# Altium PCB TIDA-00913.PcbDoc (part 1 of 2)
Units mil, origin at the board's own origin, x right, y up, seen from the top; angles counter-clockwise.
Board outline 3117.8 x 2115.91 mil, 4 copper layers (Top Layer, Internal Layer 1, Internal Layer 2, Bottom Layer), stack 61.6 mil thick; 181 components, 89 nets, 500 pads, 191 vias.
Unrouted connection lines stored in the file: 2.
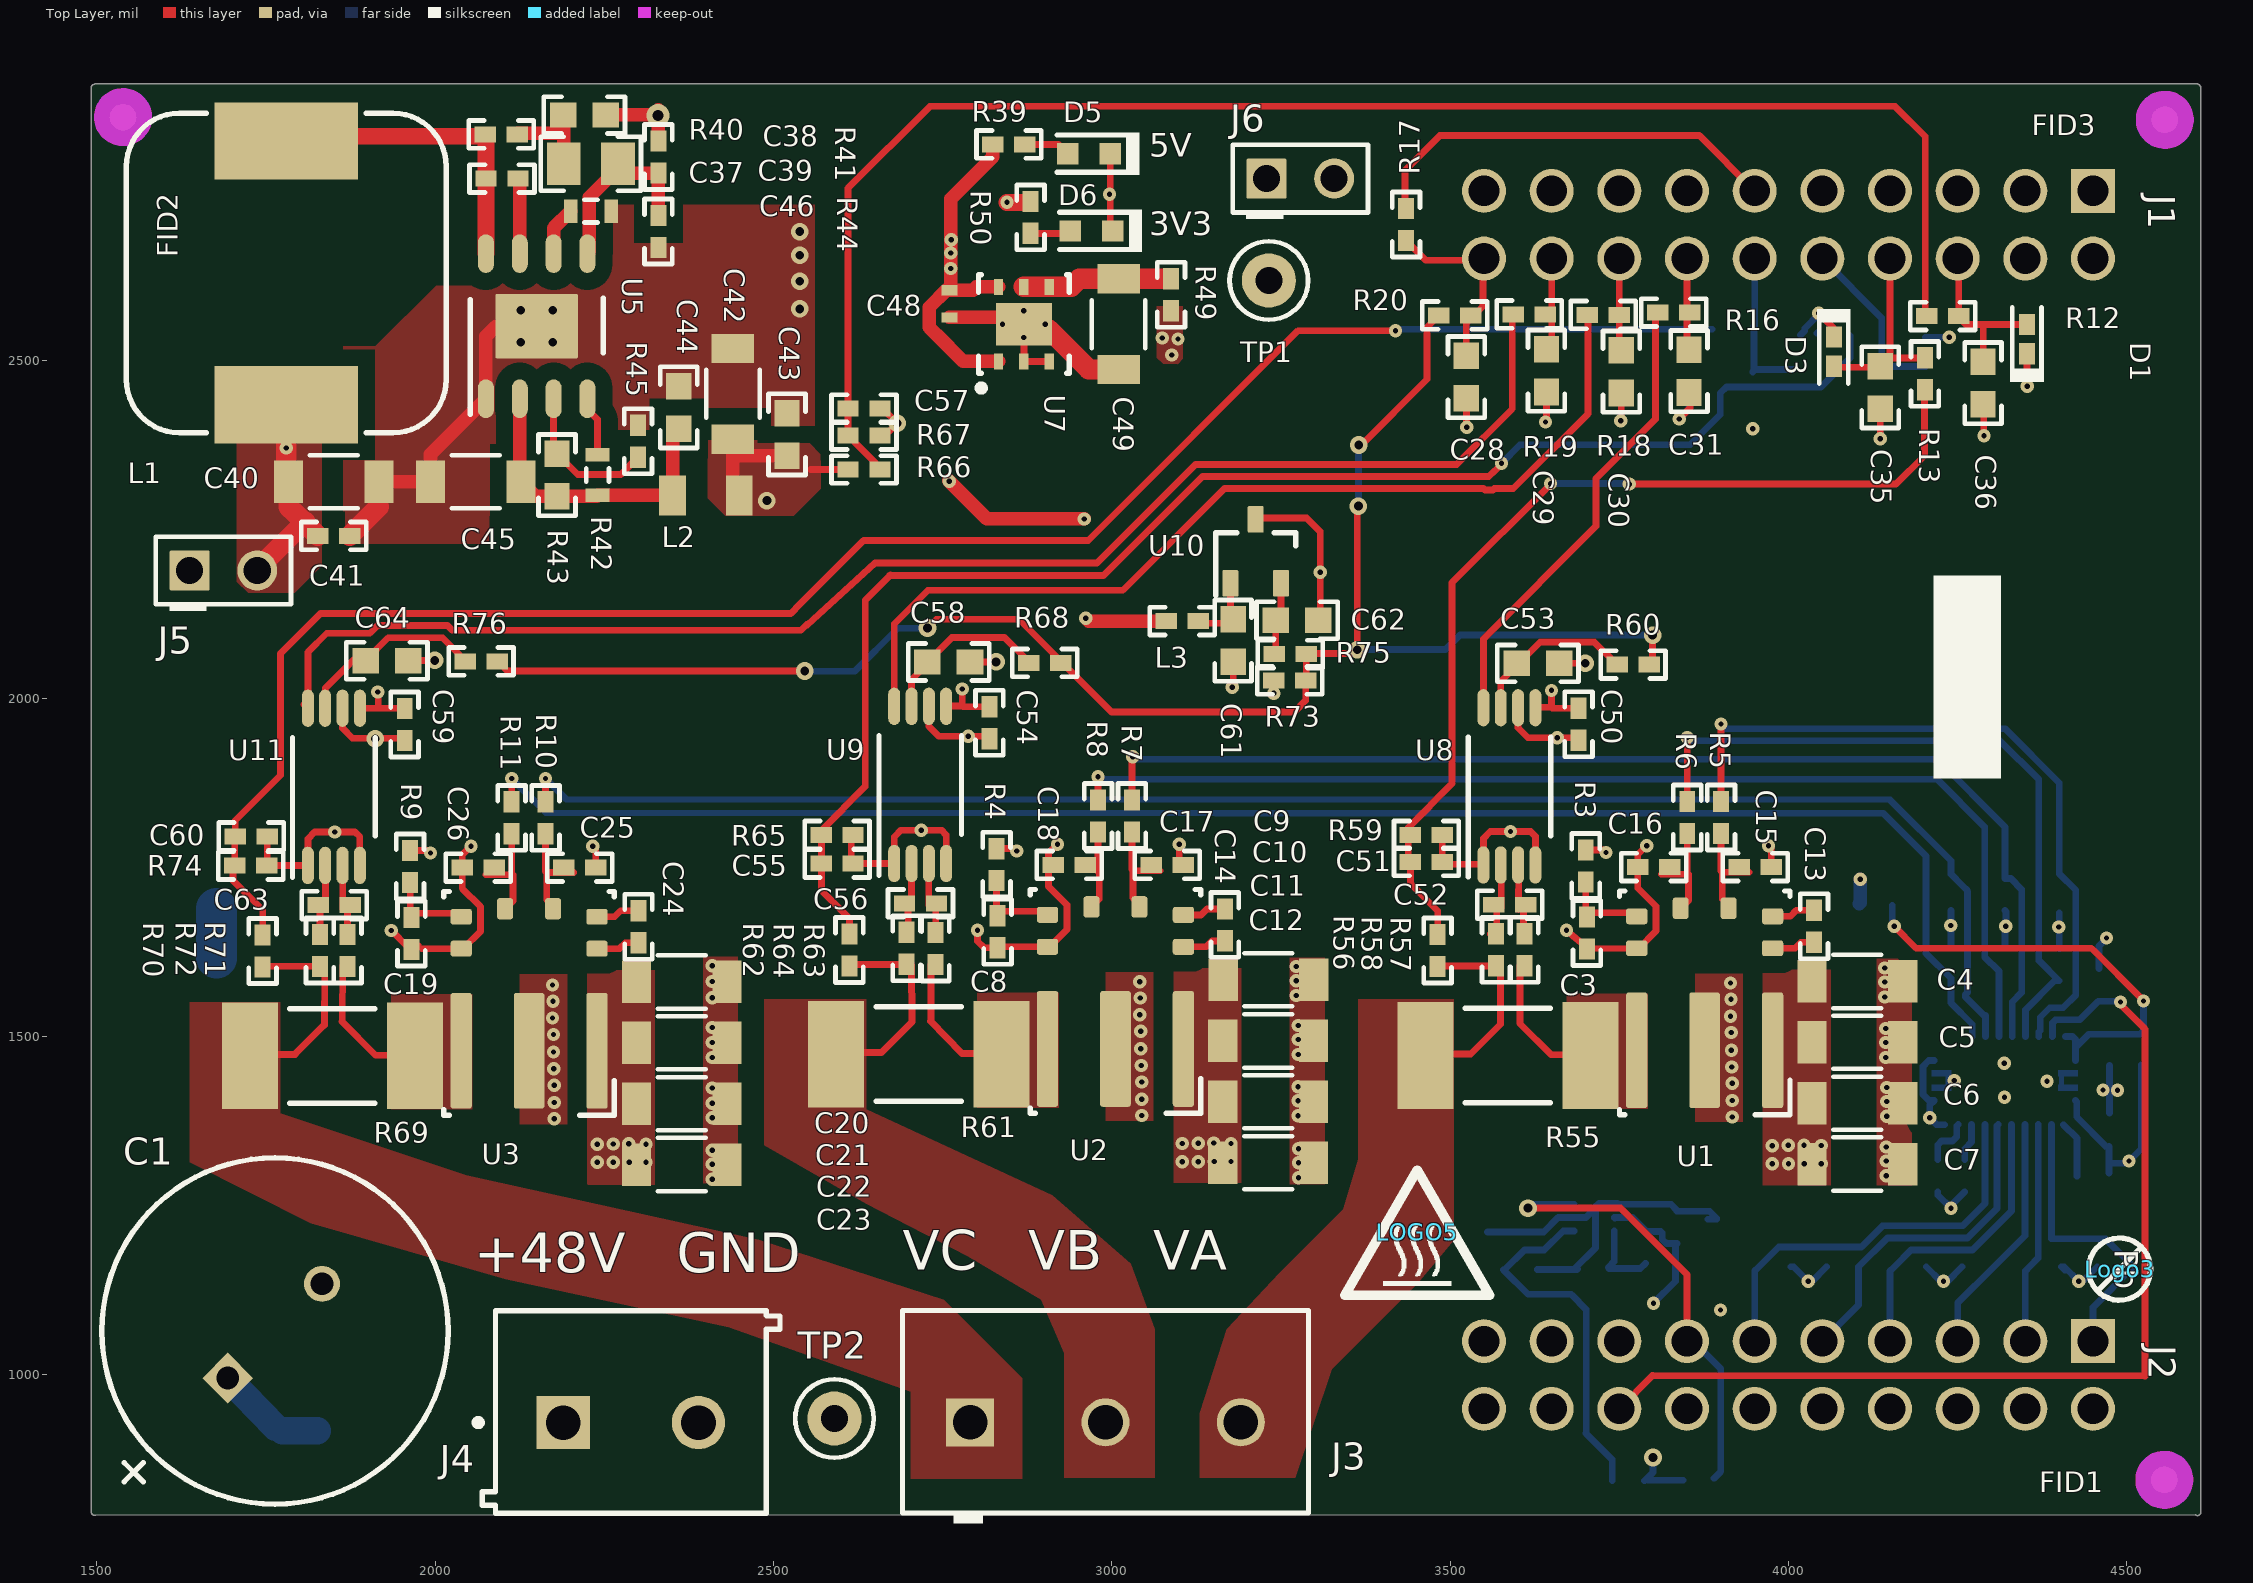
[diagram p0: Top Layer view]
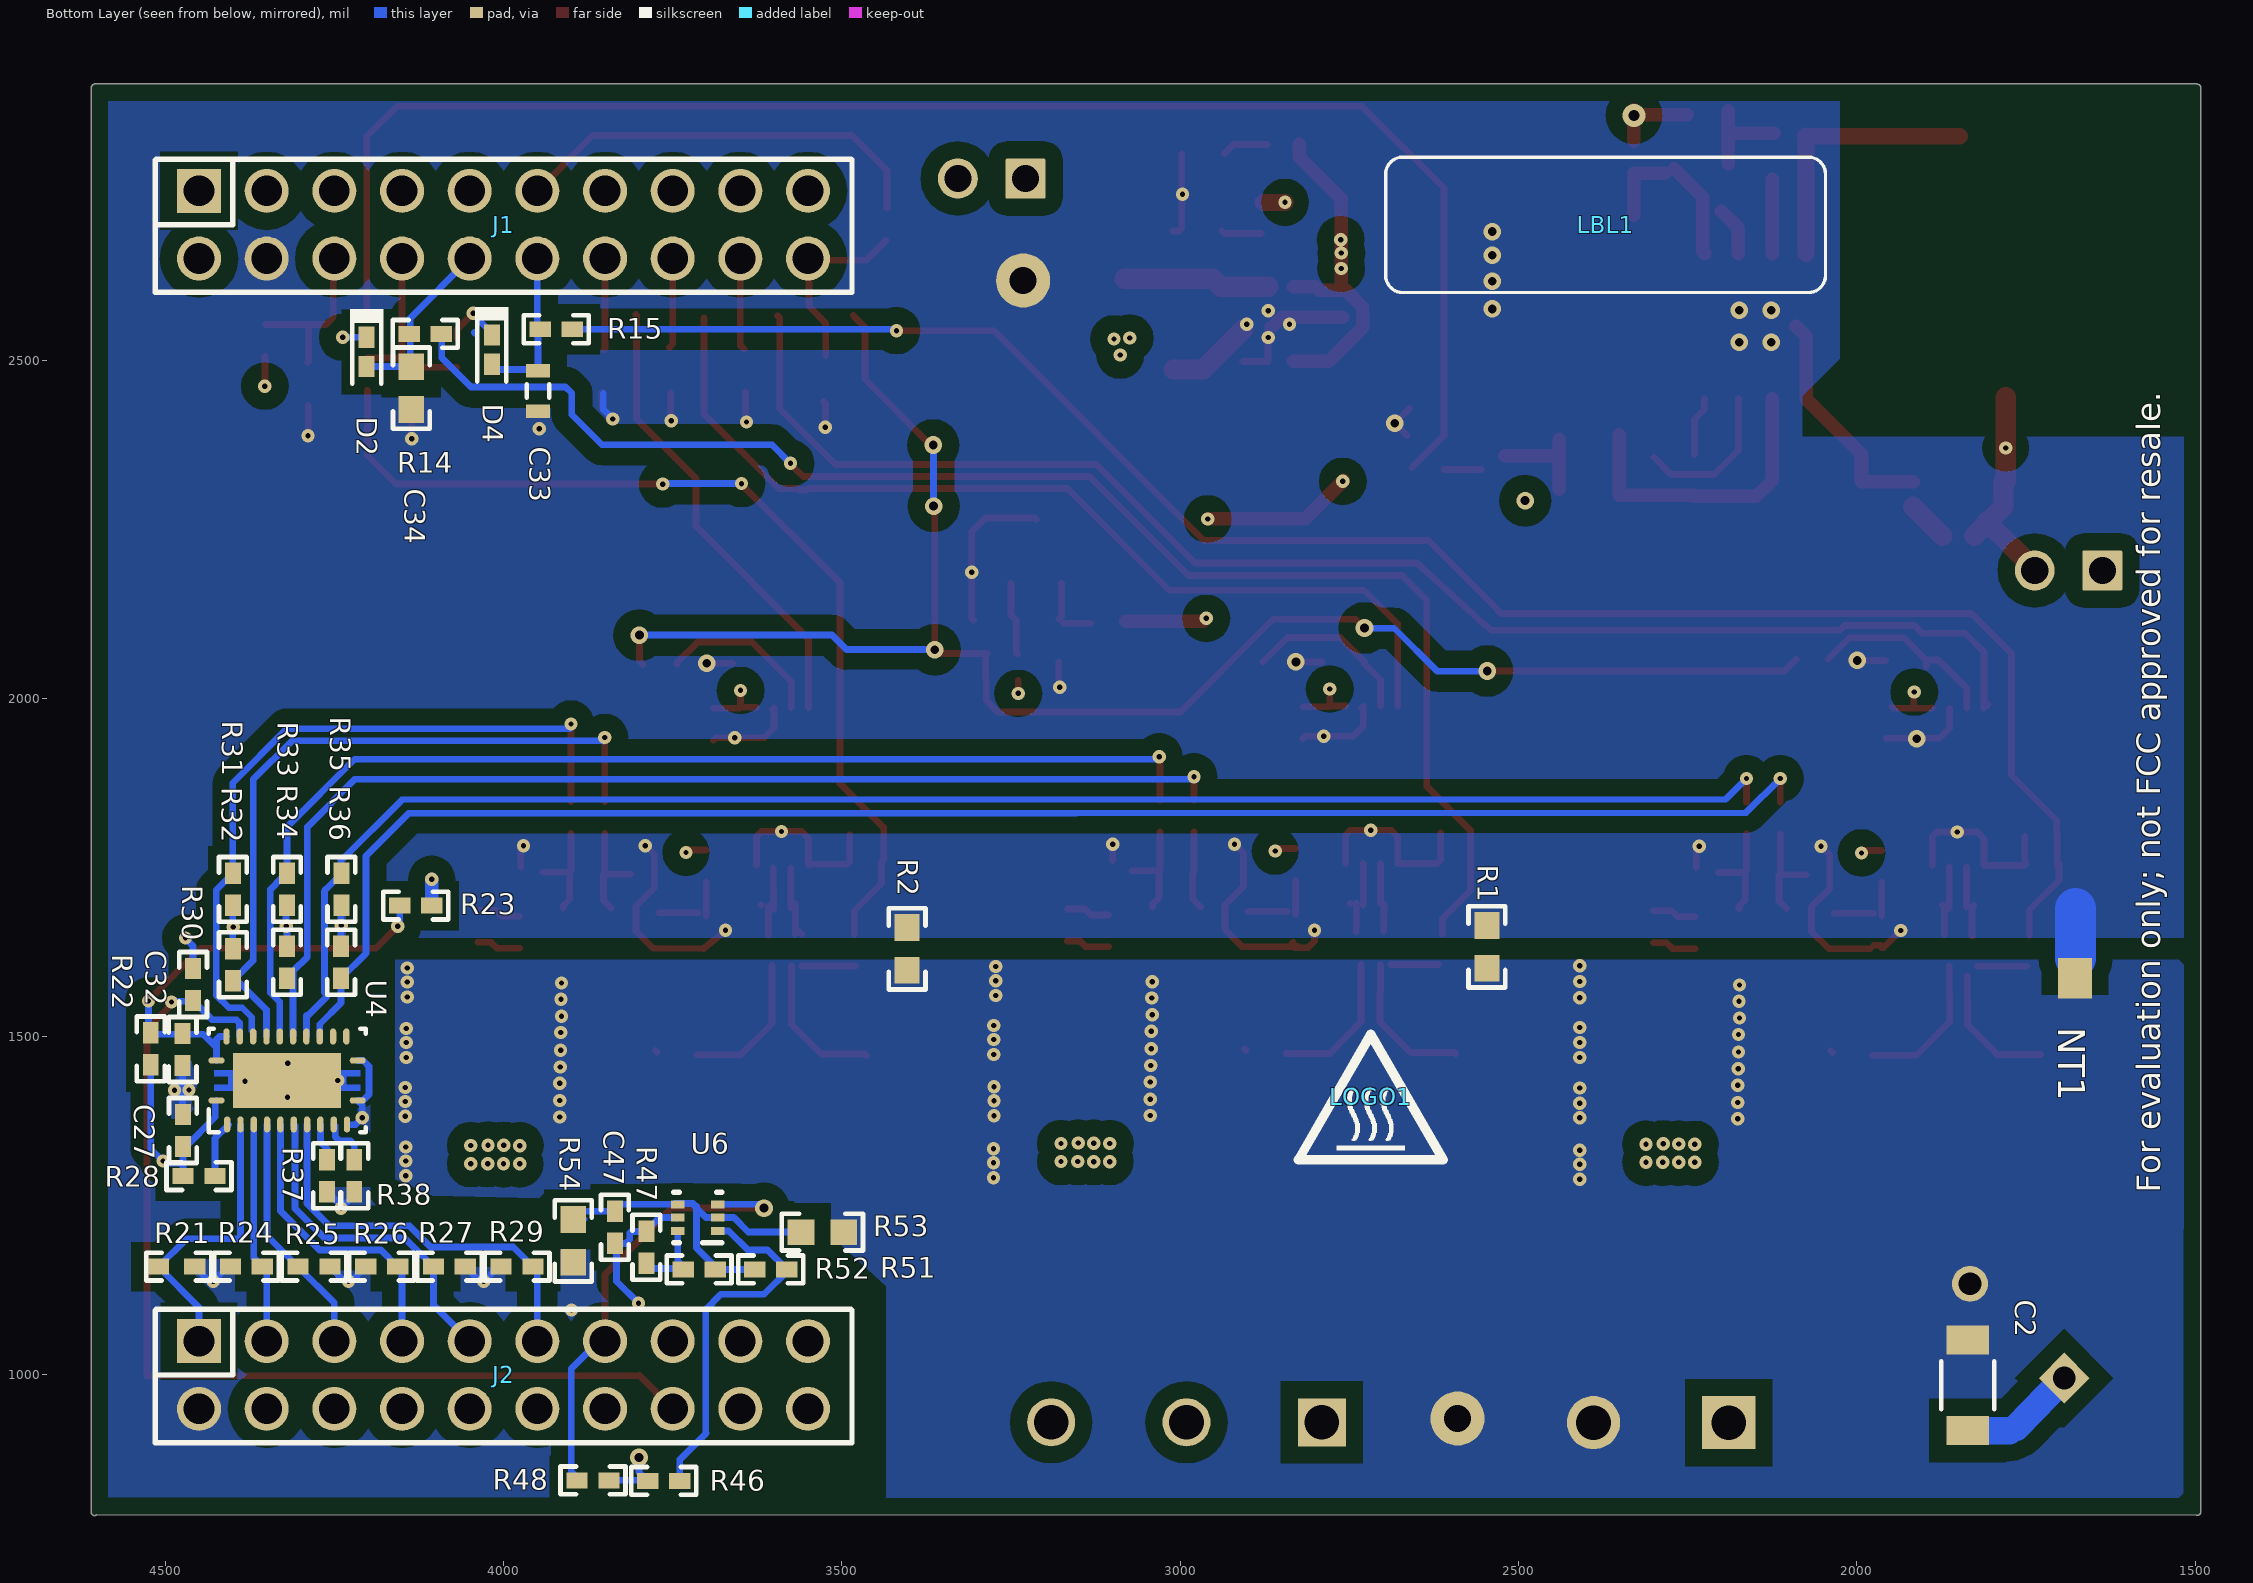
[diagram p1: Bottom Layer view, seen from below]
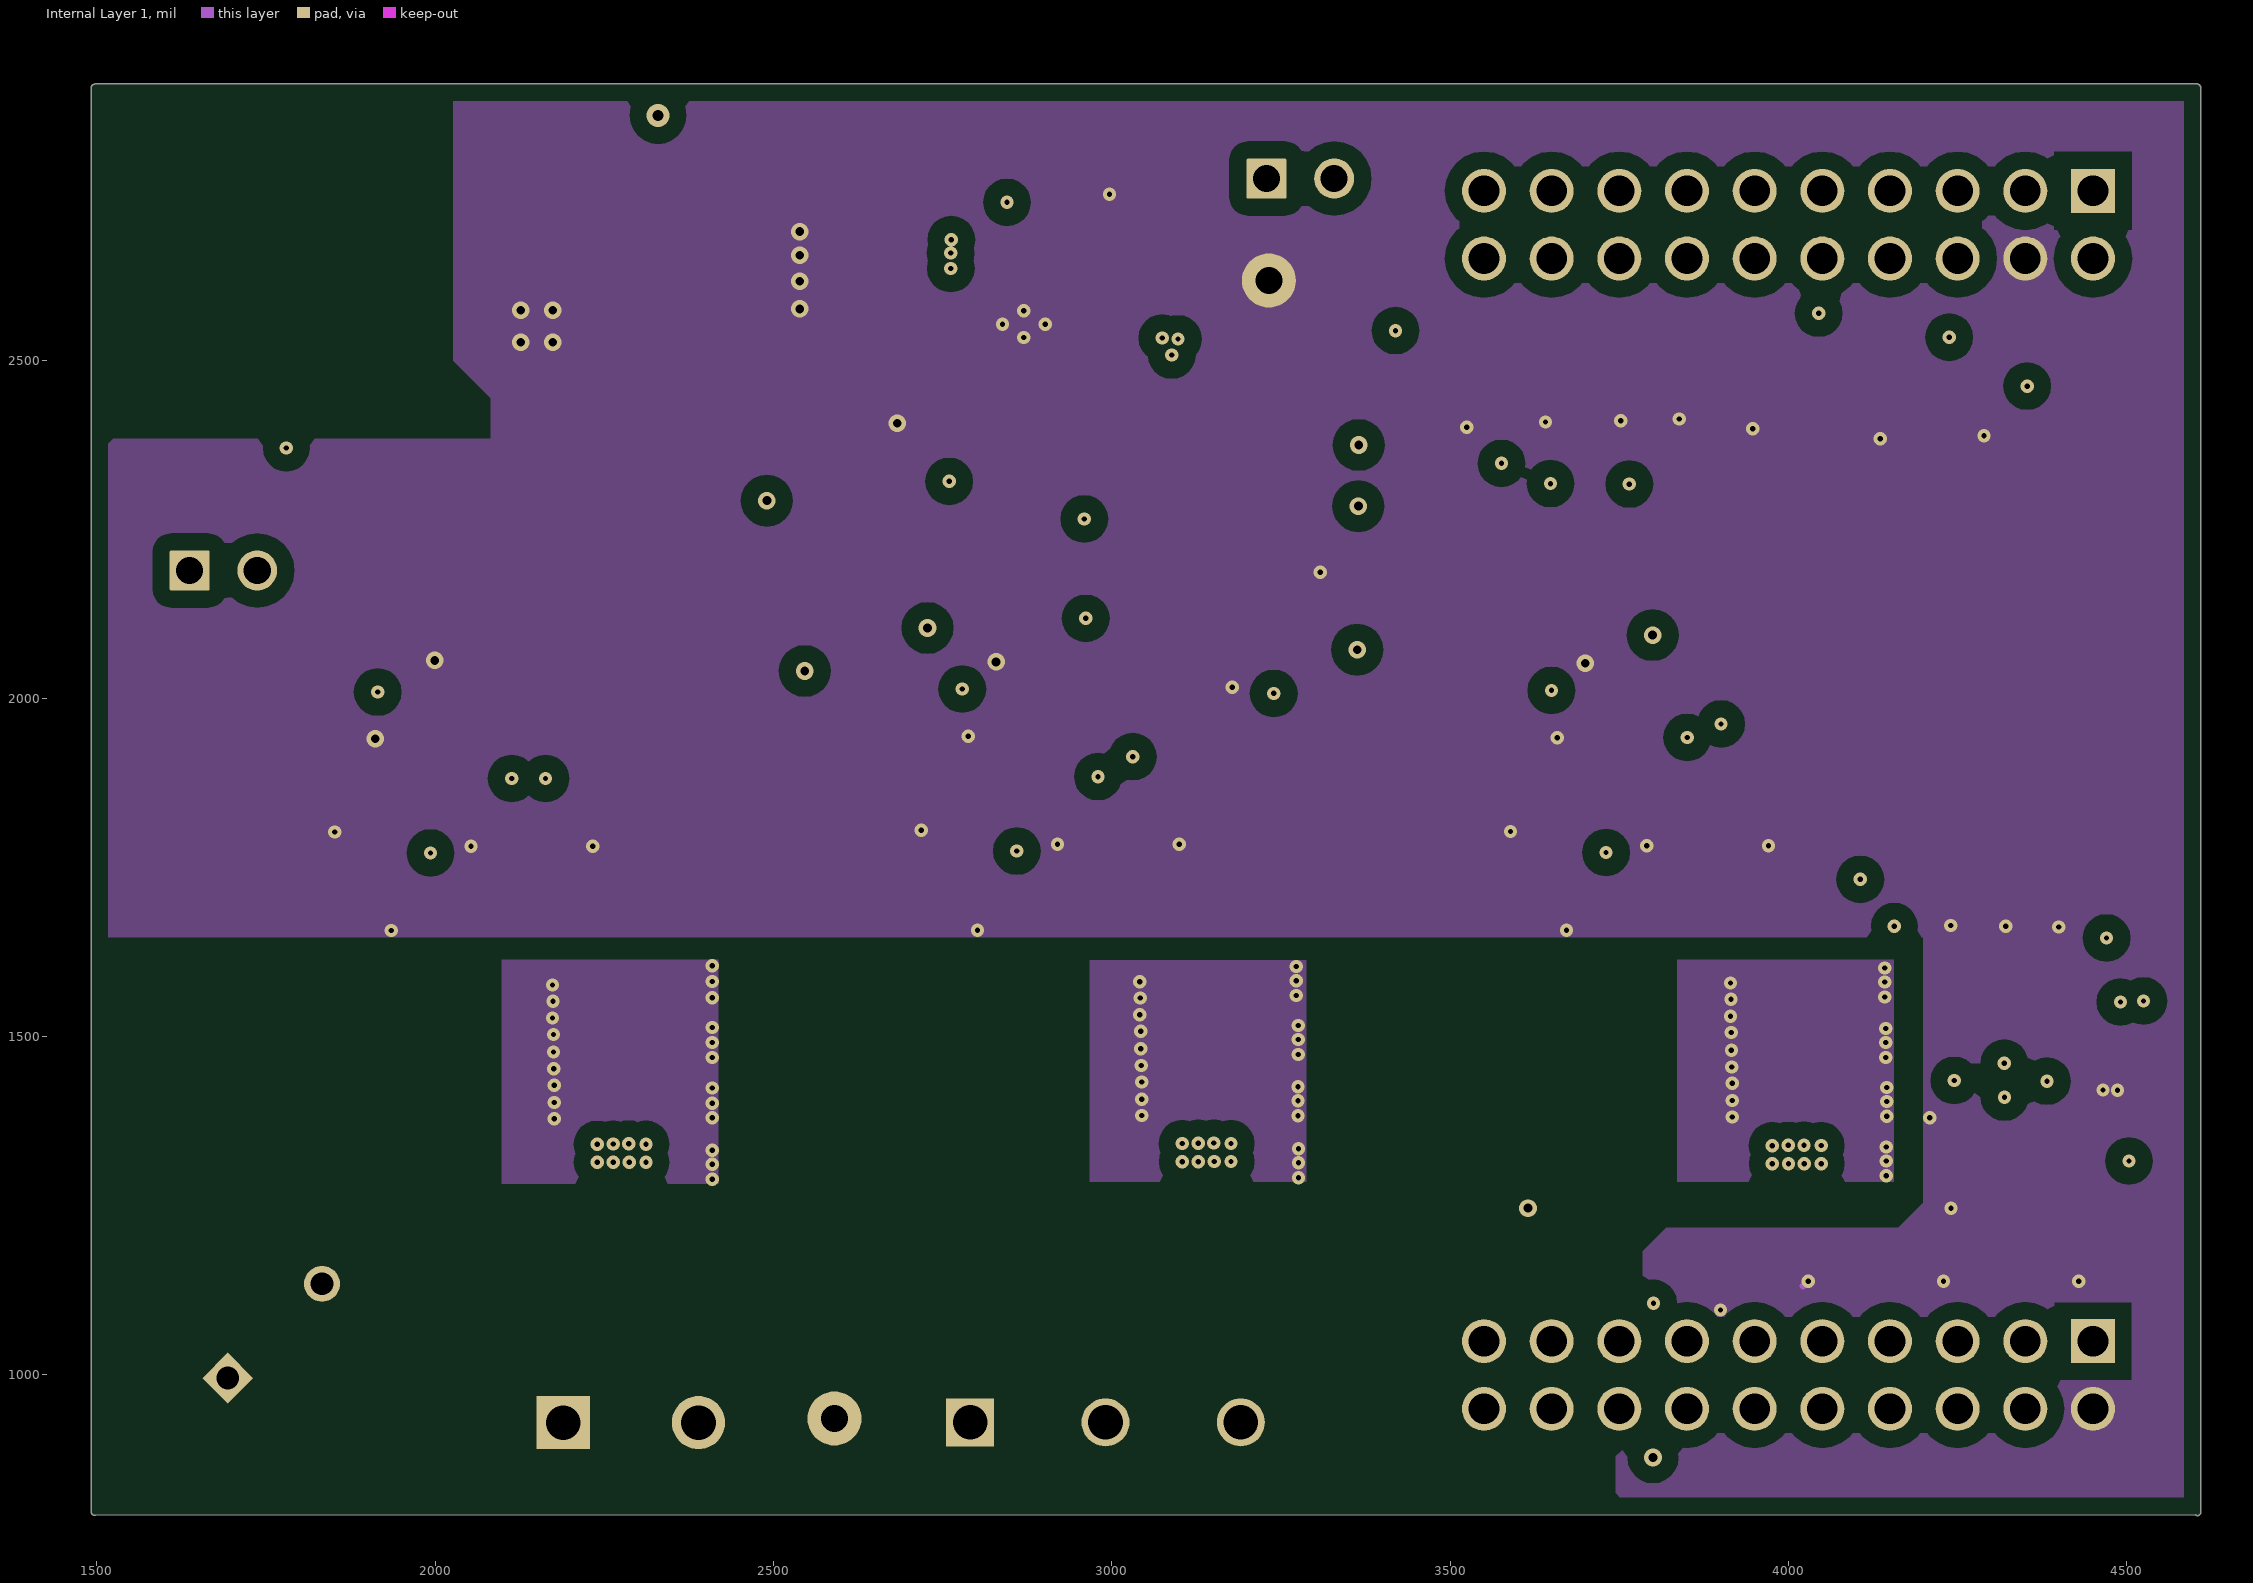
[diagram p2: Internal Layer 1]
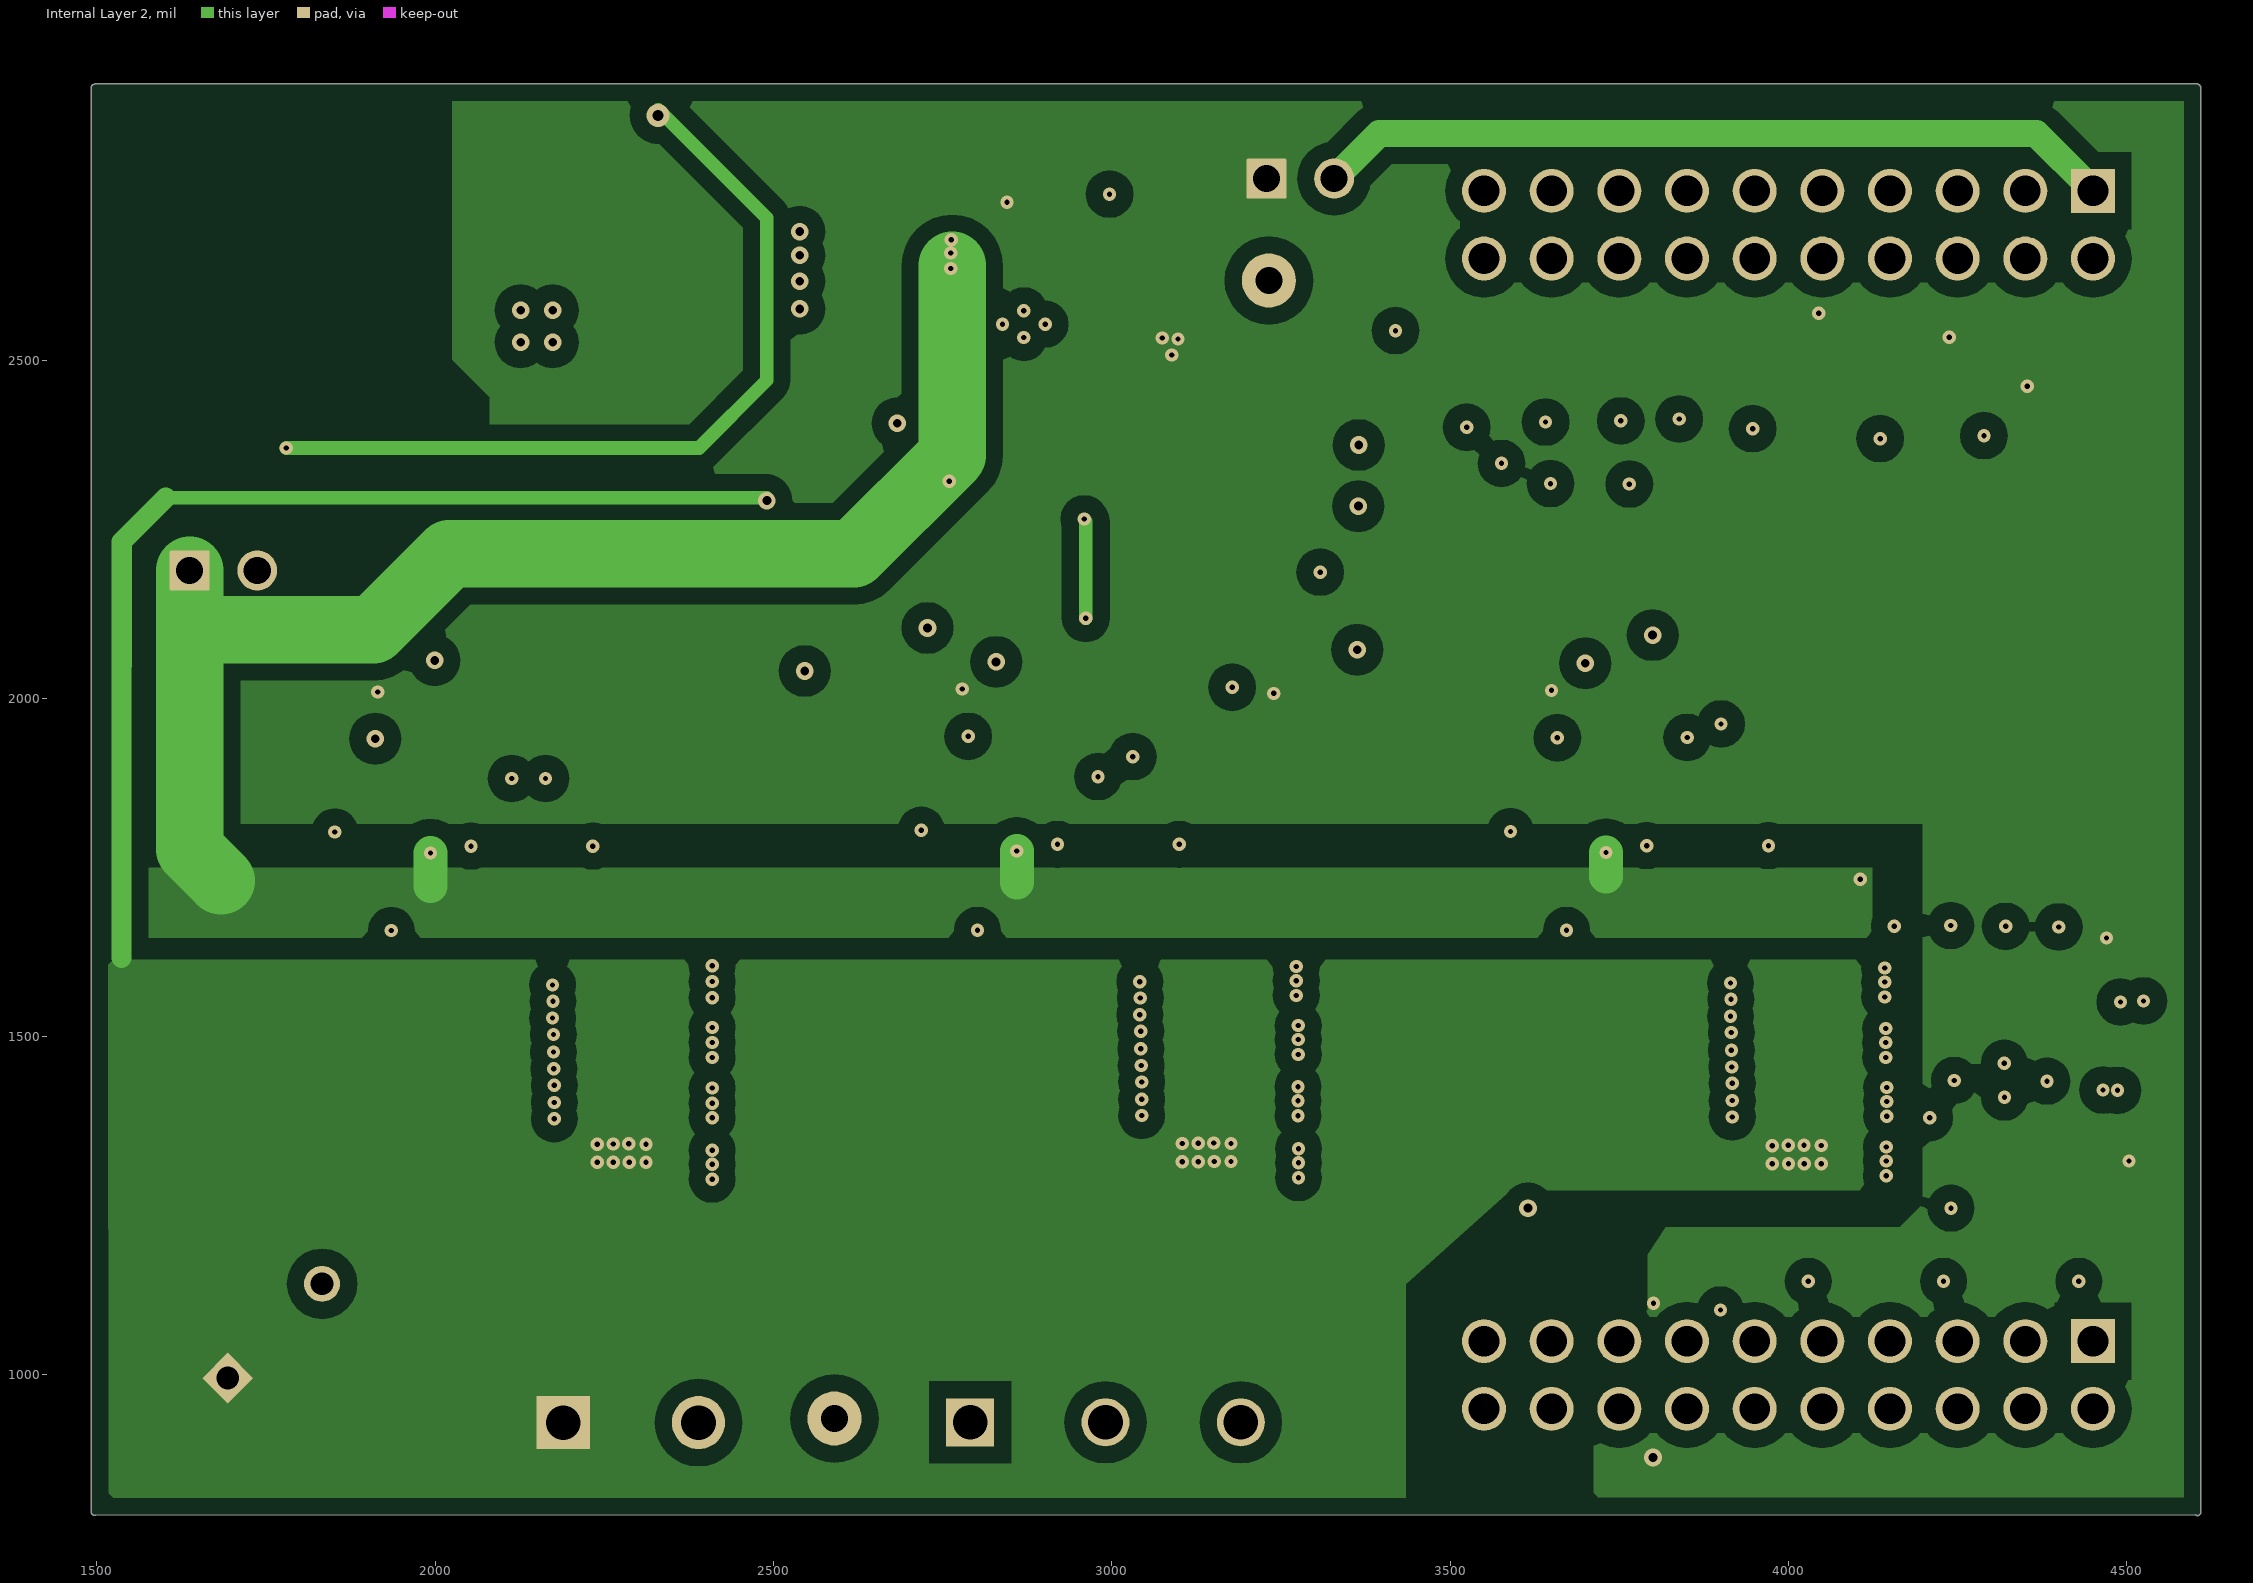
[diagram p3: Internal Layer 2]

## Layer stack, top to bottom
Top Solder: solder mask 0.4, Solder Resist, Dk 3.5
Top Layer: signal copper 1.4
Dielectric1: prepreg 10, FR-4, Dk 4.2
Internal Layer 1: signal copper 1.4
Dielectric 3: core 36, FR-4, Dk 4.2
Internal Layer 2: signal copper 1.4
Dielectric 2: prepreg 10, FR-4, Dk 4.2
Bottom Layer: signal copper 1.4
Bottom Solder: solder mask 0.4, Solder Resist, Dk 3.5

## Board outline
1491.72,797.7 ccw(c1496.73,797.7) 1497.76,792.79 4600.98,793.53 ccw(c4604.38,797.21) 4609.4,797.21 4609.4,2902.14 ccw(c4604.38,2902.14) 4607.82,2905.79 ccw(c4603.58,2903.11) 4603.58,2908.12 1498.44,2908.12 ccw(c1498.44,2903.11) 1495.82,2907.38 ccw(c1496.61,2902.43) 1491.59,2902.43

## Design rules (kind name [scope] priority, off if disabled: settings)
AcuteAngle [All] p1: minimum=4.50000000000000E+0001 checktracksonly=FALSE
AssemblyTestPointUsage [All] p1: valid=2
BoardOutlineClearance BoardOutlineClearance_MountingHoles [OnCopper and InComponentClass('Mounting Holes')] p1: gap=40
BoardOutlineClearance BoardOutlineClearance_Poly [OnCopper and InPoly] p2: gap=25
BoardOutlineClearance [OnCopper and Not InComponentClass('Logo') and not InComponentClass('FiducialMark') and not InRegion(1000,500,4000,800)] p3: gap=25
Clearance Clearance_Keepouts [((IsTrack Or IsArc) And Not InPoly) And IsFree and IsKeepOut vs ((IsTrack Or IsArc) And Not InPoly) And IsFree and IsKeepOut] p1: gap=0
Clearance Clearance_Poly [InPolygon] p2: gap=25
Clearance [All] p3: gap=7.87
ComponentClearance ComponentClearance_MountingHoles_FiducialMarks [InComponentClass('Mounting Holes') vs InComponentClass('FiducialMark')] p1: gap=50 collisioncheckmode=3 verticalgap=10 showdistances=FALSE
ComponentClearance ComponentClearance_Shunt [InComponentClass('Header') vs InComponentClass('Shunt')] p2: gap=0 collisioncheckmode=3 verticalgap=0 showdistances=FALSE
ComponentClearance ComponentClearance_Logo [InComponentClass('Logo')] p3: gap=50 collisioncheckmode=3 verticalgap=10 showdistances=FALSE
ComponentClearance ComponentClearance_ScrewToNut [(HasFootprint('NY PMS 440 0025 PH')) vs (HasFootprint('Keystone_1902C'))] p4: gap=5 collisioncheckmode=3 verticalgap=10 showdistances=FALSE
ComponentClearance ComponentClearance_MountingHoles [InComponentClass('Mounting Holes')] p5: gap=250 collisioncheckmode=3 verticalgap=100000 showdistances=FALSE
ComponentClearance ComponentClearance_SmallPassives [HasFootprint('0201*') or HasFootprint('0402*') or HasFootprint('0508') or HasFootprint('0603*') or HasFootprint('0612') or HasFootprint('0805*') or HasFootprint('0815*') or HasFootprint('0830*') or HasFootprint('1206*') or HasFootprint('1210*') or HasFootprint('1808*') or HasFootprint('1812*') or HasFootprint('1825*') or HasFootprint('2010*') or HasFootprint('2220*') or HasFootprint('2225*') or HasFootprint('2512*') or HasFootprint('2728*') or HasFootprint('3518*') vs HasFootprint('0201*') or HasFootprint('0402*') or HasFootprint('0508') or HasFootprint('0603*') or HasFootprint('0612') or HasFootprint('0805*') or HasFootprint('0815*') or HasFootprint('0830*') or HasFootprint('1206*') or HasFootprint('1210*') or HasFootprint('1808*') or HasFootprint('1812*') or HasFootprint('1825*') or HasFootprint('2010*') or HasFootprint('2220*') or HasFootprint('2225*') or HasFootprint('2512*') or HasFootprint('2728*') or HasFootprint('3518*')] p6: gap=14.96 collisioncheckmode=3 verticalgap=10 showdistances=FALSE
ComponentClearance ComponentClearance_THtoSMT [IsThruComponent vs IsSMTComponent] p7: gap=40 collisioncheckmode=3 verticalgap=30 showdistances=FALSE
ComponentClearance ComponentClearance_THtoTH [IsThruComponent vs IsThruComponent] p8: gap=30 collisioncheckmode=3 verticalgap=30 showdistances=FALSE
ComponentClearance [All] p9: gap=30 collisioncheckmode=3 verticalgap=10 showdistances=FALSE
DiffPairsRouting [All] p1: maxlimit=100 minlimit=10 mostfreqgap=10 toplayer_minwidth=15 toplayer_maxwidth=15 toplayer_prefwidth=15 midlayer1_minwidth=15 midlayer1_maxwidth=15 midlayer1_prefwidth=15 midlayer2_minwidth=15 midlayer2_maxwidth=15 midlayer2_prefwidth=15 bottomlayer_minwidth=15 bottomlayer_maxwidth=15 bottomlayer_prefwidth=15 maxuncoupledlength=1000
FabricationTestPointUsage TestPointUsage [All] p1: valid=2 allowmultiple=FALSE
FabricationTestpoint Testpoint [All] p1: side=3 testpointundercomponent=TRUE minsize=40 maxsize=100 preferedsize=60 minholesize=0 maxholesize=40 preferedholesize=32 testpointgrid=1 allowsidetop=TRUE allowsidebottom=TRUE usegrid=TRUE gridtolerance=0.01
FanoutControl Fanout_LCC [IsLCC] p1: bgadir=Out bgaviamode=Centered fanoutstyle=Auto fanoutdirection=Alternating viagrid=1 // Fanout_LCC (Default Rule)
FanoutControl Fanout_BGA [IsBGA] p2: bgadir=Out bgaviamode=Centered fanoutstyle=Auto fanoutdirection=Alternating viagrid=1 // Fanout_BGA (Default Rule)
FanoutControl Fanout_Default [All] p4: bgadir=Out bgaviamode=Centered fanoutstyle=Auto fanoutdirection=Alternating viagrid=1 // Fanout_Default (Default Rule)
FanoutControl Fanout_Small [(CompPinCount < 5)] p5: bgadir=Out bgaviamode=Centered fanoutstyle=Auto fanoutdirection=OutThenIn viagrid=1 // Fanout_Small (Default Rule)
HoleSize [All] p1: absolutevalues=TRUE maxlimit=251 minlimit=7.87 maxpercent=80.000 minpercent=20.000
MinimumAnnularRing MinimumAnnularRing_ThermalPadVias [IsVia and InAnyComponent] p1: minimumring=5.91
MinimumAnnularRing [All] p2: minimumring=5.5
MinimumSolderMaskSliver MinimumSolderMaskSliver_Logo [InComponentClass('Logo') vs InComponentClass('Logo')] p1: minsoldermaskwidth=0.7
MinimumSolderMaskSliver [All] p2: minsoldermaskwidth=3.94
PlaneClearance [All] p1: clearance=10
PlaneConnect [All] p1: planeconnectstyle=Relief reliefexpansion=10 reliefentries=4 reliefconductorwidth=10 reliefairgap=10
PolygonConnect [All] p1: connectstyle=Direct reliefconductorwidth=10 reliefentries=4 polygonreliefangle="90 Angle" airgapwidth=10
RoutingVias ThermalPadVias [IsVia and InAnyComponent] p1: holewidth=7.87 width=19.68 viastyle="Through Hole" minholewidth=7.87 minwidth=19.68 maxholewidth=12.99 maxwidth=26
RoutingVias [All] p2: holewidth=16 width=34 viastyle="Through Hole" minholewidth=5.9 minwidth=18 maxholewidth=40 maxwidth=65
SilkToBoardRegionClearance [Not ((IsComment or IsDesignator) And (Hide <> 'False')) and not InRegion(1000,500,4000,800)] p1:
SilkToSilkClearance SilkToSilkClearance_Pb-FreeLogo [(HasFootprint('Pb-Free_Overlay_Medium') OR HasFootprint('Pb-Free_Overlay_Small')) vs (HasFootprint('Pb-Free_Overlay_Medium') OR HasFootprint('Pb-Free_Overlay_Small'))] p1: silktosilkclearance=0
SilkToSilkClearance [All] p2: silktosilkclearance=4
SilkToSolderMaskClearance SilkToComponentPadClearance [IsPad and InAnycomponent] p1: minsilkscreentomaskgap=5 clearancetoexposedcopper=TRUE
SilkToSolderMaskClearance "Silk to Solder Mask Opening" [All] p2: minsilkscreentomaskgap=4 clearancetoexposedcopper=FALSE
SolderMaskExpansion [All] p1: expansion=1.97
Width [All] p1: maxlimit=100 minlimit=6 preferedwidth=10 checkconnectedcopper=TRUE
14 further rules are at their usual default settings.

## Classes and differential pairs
component class TIDA-00909_Sensing: C50 C51 C52 C53 C54 C55 C56 C57 C58 C59 C60 C61 C62 C63 C64 L3 R55 R56 R57 R58 R59 R60 R61 R62 R63 R64 R65 R66 R67 R68 R69 R70 R71 R72 R73 R74 R75 R76 R102 R103 R202 R203 R302 R303 U8 U9 U10 U11
component class TIDA-00909_PS: C37 C38 C39 C40 C41 C42 C43 C44 C45 C46 C48 C49 D5 D6 J5 J6 L1 L2 R39 R40 R41 R42 R43 R44 R45 R49 R50 U5 U7
component class TIDA-00909_Interface: C27 C28 C29 C30 C31 C32 C33 C34 C35 C36 D1 D2 D3 D4 J1 J2 J3 J4 R12 R13 R14 R15 R16 R17 R18 R19 R20 R21 R22 R23 R24 R25 R26 R27 R28 R29 R30 R31 R32 R33 R34 R35 R36 R37 R38 R1000 TP1 TP2 U4
component class TIDA-00909_GAN: C1 C2 C3 C4 C5 C6 C7 C8 C9 C10 C11 C12 C13 C14 C15 C16 C17 C18 C19 C20 C21 C22 C23 C24 C25 C26 C47 C113 C221 C222 NT1 R1 R2 R3 R4 R5 R6 R7 R8 R9 R10 R11 R46 R47 R48 R51 R52 R53 R54 U1 U2 U3 U6
component class Header: J5 J6
component class TIDA-00909_HW: FID1 FID2 FID3 LBL1 LOGO1 Logo1 Logo3 Logo4 LOGO5 LOGO? ZZ1 ZZ2 ZZ3 ZZ4
component class FiducialMark: FID1 FID2 FID3
component class AssemblyNote: ZZ1 ZZ2 ZZ3 ZZ4
component class Label: LBL1

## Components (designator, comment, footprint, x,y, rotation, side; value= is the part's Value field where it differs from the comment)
C1 "EKYB101ELL221MK25S" KYB_1250x3500 1763.2,1065.09 r45 top
C2 "C3216X7S2A335M160AB" 1206_190 1836.17,984.88 r90 bottom
C3 "C1005X5R1A225K050BC" 0402#1 3702.15,1653.11 r270 top
C4 "C3216C0G2A104J160AC" 1206_190 4101.74,1581.66 r0 top
C5 "C3216X7S2A335M160AB" 1206_190 4101.74,1491.66 r0 top
C6 "C3216X7S2A335M160AB" 1206_190 4101.74,1401.66 r0 top
C7 "C3216X7S2A335M160AB" 1206_190 4101.74,1311.66 r0 top
C8 "C1005X5R1A225K050BC" 0402#1 2831.38,1655.2 r270 top
C9 "C3216C0G2A104J160AC" 1206_190 3231.5,1584.01 r180 top
C10 "C3216X7S2A335M160AB" 1206_190 3230.97,1493.74 r0 top
C11 "C3216X7S2A335M160AB" 1206_190 3230.97,1403.74 r0 top
C12 "C3216X7S2A335M160AB" 1206_190 3230.97,1313.74 r0 top
C13 "GCM155R71C104KA55D" 0402#1 4037.8,1663.11 r90 top
C14 "GCM155R71C104KA55D" 0402#1 3167.03,1665.2 r90 top
C15 "GRM1555C1E470JA01D" 0402#1 3950.89,1750.67 r0 top
C16 "GRM1555C1E470JA01D" 0402#1 3800.89,1750.67 r180 top
C17 "GRM1555C1E470JA01D" 0402#1 3082.05,1753.86 r0 top
C18 "GRM1555C1E470JA01D" 0402#1 2937.19,1753.86 r180 top
C19 "C1005X5R1A225K050BC" 0402#1 1964.8,1652.44 r270 top
C20 "C3216C0G2A104J160AC" 1206_190 2364.39,1580.98 r180 top
C21 "C3216X7S2A335M160AB" 1206_190 2364.39,1490.98 r0 top
C22 "C3216X7S2A335M160AB" 1206_190 2364.39,1400.98 r0 top
C23 "C3216X7S2A335M160AB" 1206_190 2364.39,1310.98 r0 top
C24 "GCM155R71C104KA55D" 0402#1 2300.46,1662.44 r90 top
C25 "GRM1555C1E470JA01D" 0402#1 2213.54,1750 r0 top
C26 "GRM1555C1E470JA01D" 0402#1 2063.54,1750 r180 top
C27 "GRM155R71A104KA01D" 0402#1 4473.77,1361.33 r90 bottom
C28 "885012206036" 0603 3523.9,2474.83 r270 top
C29 "885012206036" 0603 3642.25,2484.28 r270 top
C30 "885012206036" 0603 3752.99,2482.78 r270 top
C31 "885012206036" 0603 3853.02,2483.6 r270 top
C32 "GRM155R71A104KA01D" 0402#1 4474.24,1481.03 r270 bottom
C33 "885012206036" 0603S 3948.97,2454.25 r270 bottom
C34 "885012206036" 0603 4136.24,2458.45 r270 bottom
C35 "885012206036" 0603 4135.56,2459.54 r270 top
C36 "885012206036" 0603 4287.55,2465.99 r270 top
C37 "GRM155R61C103KA01D" 0402#1 2098.65,2768.21 r180 top
C38 "GRM188R72A332KA01D" 0603 2220.61,2862.05 r180 top
C39 "GRM216R71H103KA01D" 0805_HV 2230,2790 r0 top
C40 "C3216X5R1A107M160AC" 1206_190 1850,2320 r0 top
C41 "C1005X7R1E104M050BB" 0402#1 1850,2240 r0 top
C42 "C3216X7S2A335M160AB" 1206_190 2440,2450 r90 top
C43 "GRM188R72A104KA35D" 0603 2520,2390 r90 top
C44 "GRM188R72A104KA35D" 0603 2360,2430 r90 top
C45 "C3216X7S2A335M160AB" 1206_190 2060,2320 r180 top
C46 "GRM188R71A105KA61D" 0603S 2230,2720 r0 top
C47 "GCM155R71C104KA55D" 0402#1 3835.34,1218.35 r90 bottom
C48 "GCM155C71A105KE38D" 0402_070 2760,2583.07 r270 top
C49 "GRM31CR60J107ME39L" 1206_180 3010,2553.07 r270 top
C50 "GCM155R71C104KA55D" 0402#1 3689.73,1961.74 r90 top
C51 "GRM155R71A333KA01D" 0402#1 3464.86,1758.37 r0 top
C52 "C0402H152J3GAC7867" 0402#1 3588.07,1694.96 r180 top
C53 "GRM188R71C104KA01D" 0603 3629.73,2051.74 r180 top
C54 "GCM155R71C104KA55D" 0402#1 2818.95,1963.82 r90 top
C55 "GRM155R71A333KA01D" 0402#1 2593.99,1755.78 r0 top
C56 "C0402H152J3GAC7867" 0402#1 2717.3,1697.05 r180 top
C57 "GRM155R71A333KA01D" 0402#1 2633.76,2428.21 r0 top
C58 "GRM188R71C104KA01D" 0603 2758.95,2053.82 r180 top
C59 "GCM155R71C104KA55D" 0402#1 1955.01,1961.36 r90 top
C60 "GRM155R71A333KA01D" 0402#1 1728.11,1796.04 r0 top
C61 "GRM188R71C104KA01D" 0603 3179.35,2085.4 r90 top
C62 "GRM188R71C104KA01D" 0603 3273.8,2115.4 r180 top
C63 "C0402H152J3GAC7867" 0402#1 1850.72,1694.29 r180 top
C64 "GRM188R71C104KA01D" 0603 1928.7,2055.62 r180 top
D1 "1PS79SB70,115" SOD-523 4352.29,2530.73 r90 top
D2 "1PS79SB70,115" SOD-523 4202.25,2512.03 r270 bottom
D3 "1PS79SB70,115" SOD-523 4067.02,2512.38 r270 top
D4 "1PS79SB70,115" SOD-523 4017.32,2515.43 r270 bottom
D5 "150060GS75000" WL-SMCW_GREEN 2966.17,2804.99 r180 top
D6 "150060GS75000" WL-SMCW_GREEN 2970,2690.79 r180 top
FID1 "Fiducial" Fiducial10-20 4555.45,845.08 r0 top
FID2 "Fiducial" Fiducial10-20 1538.67,2858.94 r0 top
FID3 "Fiducial" Fiducial10-20 4556.17,2855.05 r0 top
J1 "SSW-110-23-F-D" CONN_SSW-110-23-F-D 4000,2700 r0 bottom
J2 "SSW-110-23-F-D" CONN_SSW-110-23-F-D 4000,1000 r0 bottom
J3 "OSTTC032162" On-Shore_OSTTC032162 2990.63,930.02 r0 top
J4 "OSTTC022162" On-Shore_OSTTC022162 2289.13,945.41 r0 top
J5 "PEC02SAAN" CONN_PEC02SAAN 1687.04,2189.01 r0 top
J6 "PEC02SAAN" CONN_PEC02SAAN 3278.63,2768.2 r0 top
L1 "7447709471" WE-PD_1210 1779.9,2628.66 r270 top
L2 "NLFV25T-330K-PF" NLCV25 2400,2300 r180 top
L3 "74279272" 0402#1 3104.03,2114.18 r180 top
LBL1 "Size: 0.65\" x 0.20 \"" Label_650x200 2371.29,2699.85 r180 bottom
LOGO1 "CAUTION HOT SURFACE" IEC_HotSurface_Small 2718.26,1411.11 r180 bottom
Logo3 "Pb-Free Symbol" Pb-Free_Overlay_Small 4489.24,1156.51 r270 top
Logo4 "FCC disclaimer" FCC_disclaimer 24.2,4990.67 r180 bottom
LOGO5 "CAUTION HOT SURFACE" IEC_HotSurface_Small 3451.36,1210.63 r0 top
NT1 "Net-Tie" Net-Tie_50milWide_30milLong 1677.58,1586.55 r90 bottom net-tie
R1 "MCR03EZPJ000" 0603 2546.61,1632.71 r90 bottom
R2 "MCR03EZPJ000" 0603 3403.59,1629.77 r90 bottom
R3 "CRCW04020000Z0ED" 0402#1 3700.39,1752.21 r90 top
R4 "CRCW04020000Z0ED" 0402#1 2829.62,1754.29 r90 top
R5 "CRCW040220R0FKED" 0402#1 3900.39,1824.02 r90 top
R6 "CRCW040220R0FKED" 0402#1 3850.39,1824.02 r90 top
R7 "CRCW040220R0FKED" 0402#1 3029.62,1826.1 r90 top
R8 "CRCW040220R0FKED" 0402#1 2979.62,1826.1 r90 top
R9 "CRCW04020000Z0ED" 0402#1 1963.05,1751.54 r90 top
R10 "CRCW040220R0FKED" 0402#1 2163.05,1823.35 r90 top
R11 "CRCW040220R0FKED" 0402#1 2113.05,1823.35 r90 top
R12 "CRCW040220R0JNED" 0402#1 4228.09,2564.94 r0 top
R13 "CRCW040220R0JNED" 0402#1 4201.6,2479.53 r90 top
R14 "CRCW040220R0JNED" 0402#1 4115.55,2538.52 r0 bottom
R15 "CRCW040220R0JNED" 0402#1 3922.11,2545.49 r0 bottom
R16 "CRCW040220R0JNED" 0402#1 3830.29,2570.14 r0 top
R17 "CRCW040220R0JNED" 0402#1 3434.9,2700.23 r270 top
R18 "CRCW040220R0JNED" 0402#1 3726.39,2566.75 r0 top
R19 "CRCW040220R0JNED" 0402#1 3616.96,2567.57 r0 top
R20 "CRCW040220R0JNED" 0402#1 3506.89,2566.08 r0 top
R21 "CRCW040210K0JNED" 0402#2 4480,1160 r0 bottom
R22 "CRCW04020000Z0ED" 0402#1 4521.36,1481.97 r270 bottom
R23 "CRCW04020000Z0ED" 0402#1 4129.69,1693.67 r180 bottom
R24 "CRCW040210K0JNED" 0402#1 4380,1160 r180 bottom
R25 "CRCW040210K0JNED" 0402#1 4280,1160 r0 bottom
R26 "CRCW040210K0JNED" 0402#1 4180,1160 r180 bottom
R27 "CRCW040210K0JNED" 0402#1 4080,1160 r0 bottom
R28 "CRCW040210K0JNED" 0402#1 4450.05,1293.78 r180 bottom
R29 "CRCW040210K0JNED" 0402#1 3980,1160 r180 bottom
R30 "CRCW040210K0JNED" 0402#1 4458.75,1577.15 r90 bottom
R31 "CRCW040210K0JNED" 0402#1 4400,1717.71 r90 bottom
R32 "CRCW040210K0JNED" 0402#1 4400,1606.24 r270 bottom
R33 "CRCW040210K0JNED" 0402#1 4320,1717.71 r90 bottom
R34 "CRCW040210K0JNED" 0402#1 4320,1610 r270 bottom
R35 "CRCW040210K0JNED" 0402#1 4239.6,1717.71 r90 bottom
R36 "CRCW040210K0JNED" 0402#1 4240,1610 r270 bottom
R37 "CRCW040210K0JNED" 0402#1 4260.59,1294.6 r90 bottom
R38 "CRCW040210K0JNED" 0402#1 4220.59,1294.6 r90 bottom
R39 "CRCW04021K20JNED" 0402#1 2847.85,2818.56 r180 top
R40 "CRCW0402470KJNED" 0402#1 2097.69,2833.53 r0 top
R41 "CRCW040210K0FKED" 0402#1 2330,2800 r90 top
R42 "RC0603FR-07510KL" 0603S 2240,2330 r90 top
R43 "CRCW0603100KJNEA" 0603 2180,2330 r90 top
R44 "CRCW04023K24FKED" 0402#1 2330,2690 r90 top
R45 "CRCW040220K0JNED" 0402#1 2300,2380 r270 top
R46 "CRCW04020000Z0ED" 0402#1 3763.11,843.67 r0 bottom
R47 "CRCW04020000Z0ED" 0402#1 3788.75,1188.7 r90 bottom
R48 "CRCW040210K0FKED" 0402#1 3867.82,844.4 r180 bottom
R49 "CRCW04020000Z0ED" 0402#1 3087.79,2596.45 r270 top
R50 "CRCW0402820RJNED" 0402#1 2880,2710.79 r90 top
R51 "CRCW04020000Z0ED" 0402#1 3605.08,1156.08 r180 bottom
R52 "CRCW04020000Z0ED" 0402#1 3710.92,1156.08 r0 bottom
R53 "MCR03EZPJ000" 0603 3528.78,1211.12 r0 bottom
R54 "MCR03EZPJ000" 0603 3896.96,1198.21 r90 bottom
R55 "CRE2512-FZ-R005E-3" CRE2512-R5_R9 3585.39,1472.21 r180 top
R56 "CRCW0402100KFKED" 0402#1 3481.49,1627.24 r270 top
R57 "CRCW04020000Z0ED" 0402#1 3609.8,1628.32 r270 top
R58 "CRCW04020000Z0ED" 0402#1 3567.65,1628.32 r270 top
R59 "CRCW04024K22FKED" 0402#1 3464.86,1798.37 r180 top
R60 "CRCW04020000Z0ED" 0402#1 3770.39,2049.79 r180 top
R61 "CRE2512-FZ-R005E-3" CRE2512-R5_R9 2714.62,1474.29 r180 top
R62 "CRCW0402100KFKED" 0402#1 2612.27,1628.18 r270 top
R63 "CRCW04020000Z0ED" 0402#1 2739.39,1630.33 r270 top
R64 "CRCW04020000Z0ED" 0402#1 2696.64,1630.81 r270 top
R65 "CRCW04024K22FKED" 0402#1 2593.99,1798.24 r180 top
R66 "CRCW0402100KFKED" 0402#1 2633.76,2338.21 r180 top
R67 "CRCW04024K22FKED" 0402#1 2633.76,2388.21 r180 top
R68 "CRCW04020000Z0ED" 0402#1 2900.8,2052.56 r180 top
R69 "CRE2512-FZ-R005E-3" CRE2512-R5_R9 1848.05,1471.54 r180 top
R70 "CRCW0402100KFKED" 0402#1 1745.12,1626.67 r270 top
R71 "CRCW04020000Z0ED" 0402#1 1870.5,1627.45 r270 top
R72 "CRCW04020000Z0ED" 0402#1 1829.67,1627.45 r270 top
R73 "CRCW04020000Z0ED" 0402#1 3262.89,2026.42 r180 top
R74 "CRCW04024K22FKED" 0402#1 1727.4,1752.81 r180 top
R75 "CRCW04020000Z0ED" 0402#1 3263.8,2065.4 r0 top
R76 "CRCW04020000Z0ED" 0402#1 2067.9,2054.53 r180 top
TP1 "5001" Keystone5001 3232.04,2617.48 r90 top
TP2 "5001" Keystone5001 2590.07,935.66 r90 top
U1 "LMG5200MOFT" MOF0009A 3876.15,1549.96 r180 top
U2 "LMG5200MOFT" MOF0009A 3005.38,1552.05 r180 top
U3 "LMG5200MOFT" MOF0009A 2138.8,1549.29 r180 top
U4 "SN74AVC8T245RHLR" RHL0024A 4319.84,1435.28 r90 bottom
U5 "LM5018MRX/NOPB" DDA0008B_N 2150,2550 r90 top
U6 "TMP302BQDRLRQ1" DRL0006A 3712.92,1232.64 r0 bottom
U7 "LP38691SD-3.3/NOPB" SDE06A_full 2870,2553.07 r90 top
U8 "INA240A1PW" PW0008A_N 3587.57,1869.96 r90 top
U9 "INA240A1PW" PW0008A_N 2716.8,1872.05 r90 top
U10 "REF3333AIDBZR" DBZ0003A_N 3212.6,2217.24 r90 top
U11 "INA240A1PW" PW0008A_N 1850.22,1869.29 r90 top
ZZ1 "This Assembly Note is for PCB labels only" AssemblyNoteLabel 185,3938 r0 top
ZZ2 "These assemblies are ESD sensitive, ESD precautions shall be observed." AssemblyNote 185,3829.11 r0 top
ZZ3 "These assemblies must be clean and free from flux and all contaminants. Use of no clean flux is not acceptable." AssemblyNote 185,3740.56 r0 top
ZZ4 "These assemblies must comply with workmanship standards IPC-A-610 Class 2, unless otherwise specified." AssemblyNote 185,3652 r0 top

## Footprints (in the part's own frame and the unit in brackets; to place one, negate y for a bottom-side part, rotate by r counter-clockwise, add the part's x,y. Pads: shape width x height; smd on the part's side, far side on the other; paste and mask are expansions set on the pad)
0402#1 [mm] "0402 from SM-752 data"
  rect 0.8x0.6 smd: 1(-0.6,0) 2(0.6,0)
  silkscreen extent -1.22,-0.52 1.22,0.52, body extent -0.55,-0.3 0.55,0.3, height 0.6
0402#2 [mm] "0402 from SM-752 data"
  rect 0.8x0.6 smd: 1(-0.6,0) 2(0.762,0)
  silkscreen extent -1.22,-0.52 1.22,0.52, body extent -0.55,-0.3 0.55,0.3, height 0.6
0402_070 [mil] "SMD, 2-Leads, Body 1.2x0.7mm, Height 0.7mm"
  rect 15x24 smd: 1(-20,0) 2(20,0)
  body extent -24,-14 24,14, height 28
0603 [mm] "0603 from SM-752 data"
  rect 1x0.95 smd: 1(-0.8,0) 2(0.8,0)
  silkscreen extent -1.52,-0.69 1.52,0.69, body extent -0.87,-0.47 0.87,0.47, height 1
0603S [mil]
  rect 20x35 smd: 1(-30,0) 2(30,0)
  silkscreen extent -10,-17 10,17, body extent -34,-19 34,19, height 39
0805_HV [mil] "0805 with 30mil clearance between pads"
  rect 50x63 smd: 1(-40,0) 2(40,0)
  silkscreen extent -74,-40 74,40, body extent -43,-29 43,29, height 57
1206_180 [mm] "1206_180"
  rect 1.1x1.6 smd: 1(-1.7,0) 2(1.7,0)
  silkscreen extent -0.9,-1 0.9,1, body extent -1.75,-0.95 1.75,0.95, height 1.8
1206_190 [mm] "1206_190"
  rect 1.1x1.6 smd: 1(-1.7,0) 2(1.7,0)
  silkscreen extent -0.9,-1 0.9,1, body extent -1.75,-0.95 1.75,0.95, height 1.9
AssemblyNote [mil] "Assembly Note"
AssemblyNoteLabel [mil] "Assembly Note for PCB Labels"
CONN_PEC02SAAN [mm] "SULLINS"
  rrect7% 1.5x1.5 hole 1.016: 1(-1.27,0)
  round 1.5 hole 1.016: 2(1.27,0)
  silkscreen extent -2.54,-1.52 2.54,1.27, body extent -2.54,-1.27 2.54,1.27, height 8.38
CONN_SSW-110-23-F-D [mm] "SAMTEC"
  rect 1.65x1.65 hole 1.15: 1(11.43,-1.27)
  round 1.65 hole 1.15: 2(11.43,1.27) 3(8.89,-1.27) 4(8.89,1.27) 5(6.35,-1.27) 6(6.35,1.27) 7(3.81,-1.27) 8(3.81,1.27) 9(1.27,-1.27) 10(1.27,1.27) 11(-1.27,-1.27) 12(-1.27,1.27) 13(-3.81,-1.27) 14(-3.81,1.27) 15(-6.35,-1.27) 16(-6.35,1.27) 17(-8.89,-1.27) 18(-8.89,1.27) 19(-11.43,-1.27) 20(-11.43,1.27)
  silkscreen extent -13.08,-2.46 13.08,2.54, body extent -13,-2.51 13,2.54, height 8.59
CRE2512-R5_R9 [mm] "SMD, 2-Leads, Body 6.45x3.35mm, Pitch 6.2mm"
  rect 2.1x4 smd: 1(-3.1,0) 2(3.1,0)
  silkscreen extent -1.6,-1.78 1.6,1.78, body extent -3.32,-1.77 3.32,1.77, height 0.9
DBZ0003A_N [mm] "SOT23, 3-Leads, Body 2.9x1.3mm, Pitch 0.95mm, Lead Span 2.4mm, IPC Medium Density"
  rrect17% 1x0.6 smd: 1(-1.2,0.95) 2(-1.2,-0.95) 3(1.2,0)
  silkscreen extent -1.65,-1.5 0.7,1.5, body extent -1.26,-1.46 1.26,1.46, height 0.98
DDA0008B_N [mm] "SOIC, 8-Leads, Body 4.9x3.9mm, Pitch 1.27mm, Exposed Pad, IPC Medium Density"
  rrect100% 1.45x0.6 smd: 1(-2.725,1.905) 2(-2.725,0.635) 3(-2.725,-0.635) 4(-2.725,-1.905) 5(2.725,-1.905) 6(2.725,-0.635) 7(2.725,0.635) 8(2.725,1.905)
  rrect4% 2.41x3.1 smd: 9(0,0)
  silkscreen extent -3.3,-2.5 1.05,2.5, body extent -2.98,-2.45 2.98,2.45, height 1.55
DRL0006A [mm] "SOTFL, 6-Flat Leads, Body 1.2x1.6x0.6mm, Pitch 0.5mm, TI recommended"
  rect 0.5x0.3 smd: 1(-0.75,0.5) 2(-0.75,0) 3(-0.75,-0.5) 4(0.75,-0.5) 5(0.75,0) 6(0.75,0.5)
  silkscreen extent -0.9,-0.95 0.9,0.95, body extent -0.85,-0.85 0.85,0.85, height 0.62
FCC_disclaimer [mil]
Fiducial10-20 [mm]
  round 1 smd mask+0.5: 1(0,0)
  Top Layer keep-out circle w1.178: c0,0 r0.5
IEC_HotSurface_Small [mil]
  silkscreen extent -107,-93 107,92
Keystone5001 [mil] "For Keystone 500x miniature loop terminals"
  round 80 hole 40: 1(0,0)
  silkscreen extent -58,-58 58,58, body extent -49,-49 49,49, height 182
KYB_1250x3500 [mm] "TH, 2-Leads, Dia 12.5mm, Lead Spacing 5mm"
  rect 1.35x1.35 hole 0.85: 1(-2.5,0)
  round 1.35 hole 0.85: 2(2.5,0)
  silkscreen extent -8,-6.5 6.5,6.5, body extent -6.5,-6.5 6.51,6.5, height 36.51
Label_650x200 [mil] "Thermal Transfer Label"
  silkscreen extent -325,-100 325,100, body extent -325,-100 325,100, height 1
MOF0009A [mm] "SIP, 6X8mm,  TI Recommended"
  rrect25% 0.8x4.35 smd paste-1.5 mask-0.05: 1(-2.55,1.78) 8(2.55,1.78)
  rrect17% 0.7x0.59 on Top Paste: 1A(-2.55,3.56) 1B(-2.55,2.67) 1C(-2.55,1.78) 1D(-2.55,0.89) 1E(-2.55,0) 8A(2.55,3.56) 8B(2.55,2.67) 8C(2.55,1.78) 8D(2.55,0.89) 8E(2.55,0)
  rrect33% 0.8x0.6 smd mask-0.05: 2(-2.55,-2.05) 3(-2.55,-3.25) 6(2.55,-3.25) 7(2.55,-2.05)
  rrect33% 0.6x0.8 smd mask-0.05: 4(-0.9,-3.55) 5(0.9,-3.55)
  rrect17% 1.15x4.35 smd paste-1.5 mask-0.05: 9(0,1.78)
  rrect17% 1.05x0.59 on Top Paste: 9A(0,3.56) 9B(0,2.67) 9C(0,1.78) 9D(0,0.89) 9E(0,0)
  silkscreen extent -3.2,-4.2 3.2,4.2, body extent -3,-4 3,4, height 1.92
Net-Tie_50milWide_30milLong [mil] "50mil net tie, no solder mask opening, no solder paste"
  rect 30x50 smd paste-20 mask-20: 1(-15,0) 2(15,0)
NLCV25 [mm] "TDK"
  rect 1x1.5 smd: 1(-1.25,0) 2(1.25,0)
  body extent -1.35,-1.05 1.35,1.05, height 1.9
On-Shore_OSTTC022162 [mm] "THD, 2-Leads, Body 10.16x7.6mm, Pitch 5.08mm"
  rect 2x2 hole 1.3: 1(-2.54,-0.4)
  round 2 hole 1.3: 2(2.54,-0.4)
  silkscreen extent -5.85,-3.8 5.6,3.8, body extent -5.58,-3.8 5.6,3.8, height 10.31
On-Shore_OSTTC032162 [mm] "Terminal Block, 3x1, 5.08 mm, TH"
  rect 1.8x1.8 hole 1.3: 1(-5.08,0)
  round 1.8 hole 1.3: 2(0,0) 3(5.08,0)
  silkscreen extent -7.62,-3.8 7.62,4.2, body extent -7.62,-3.3 7.62,4.2, height 10
Pb-Free_Overlay_Small [mil]
  silkscreen extent -46,-46 46,46
PW0008A_N [mm] "TSOP, 8-Leads, Body 3x4.4mm, Pitch 0.65mm, IPC Medium Density"
  oval 1.4x0.45 smd: 1(-2.95,0.975) 2(-2.95,0.325) 3(-2.95,-0.325) 4(-2.95,-0.975) 5(2.95,-0.975) 6(2.95,-0.325) 7(2.95,0.325) 8(2.95,0.975)
  silkscreen extent -3.4,-1.55 1.85,1.55, body extent -3.21,-1.5 3.21,1.5, height 1.2
RHL0024A [mm]
  oval 0.24x0.6 smd: 1(-0.75,2.65) 12(-0.75,-2.65) 13(0.75,-2.65) 24(0.75,2.65)
  oval 0.6x0.24 smd: 2(-1.65,2.25) 3(-1.65,1.75) 4(-1.65,1.25) 5(-1.65,0.75) 6(-1.65,0.25) 7(-1.65,-0.25) 8(-1.65,-0.75) 9(-1.65,-1.25) 10(-1.65,-1.75) 11(-1.65,-2.25) 14(1.65,-2.225) 15(1.65,-1.725) 16(1.65,-1.225) 17(1.65,-0.725) 18(1.65,-0.225) 19(1.65,0.275) 20(1.65,0.775) 21(1.65,1.275) 22(1.65,1.775) 23(1.65,2.275)
  rect 2.05x4.05 smd paste-1.1: 25(0,0)
  Top Layer region: -0.395,-2.024 0.395,-2.024 0.395,-2.225 -0.395,-2.225
  Top Layer region: -0.396,2.75 -0.154,2.75 -0.154,2 -0.396,2
  Top Layer region: 0.152,2.75 0.394,2.75 0.394,2 0.152,2
  Top Layer region: -0.395,2.225 0.395,2.225 0.395,2.024 -0.395,2.024
  Top Layer region: -0.152,-2.75 -0.394,-2.75 -0.394,-2 -0.152,-2
  Top Layer region: 0.396,-2.75 0.154,-2.75 0.154,-2 0.396,-2
  silkscreen extent -1.95,-2.95 1.95,2.95, body extent -1.82,-2.82 1.82,2.82, height 1.01
SDE06A_full [mm] "SON, 6-Leads, Body 3x3 mm, Pitch 0.95mm, Full Paste, NSC Recommended"
  rect 0.6x0.35 smd paste-0.175 mask+0.051: 1(-1.4,0.95) 2(-1.4,0) 3(-1.4,-0.95) 4(1.4,-0.95) 5(1.4,0) 6(1.4,0.95)
  rect 1.6x2.1 smd paste-0.8 mask+0.051: 7(0,0)
  silkscreen extent -2.52,-1.7 1.85,1.72, body extent -1.55,-1.55 1.55,1.55, height 0.8
SOD-523 [mm] "NXP Semiconductor recommended land pattern, nominal STEP model"
  rect 0.8x0.6 smd paste-0.05: 1(-0.55,0) 2(0.55,0)
  silkscreen extent -1.6,-0.64 1.2,0.63, body extent -0.8,-0.4 0.8,0.4, height 0.72
WE-PD_1210 [mm] "Wurth Elektronik recommended land pattern"
  rect 2.9x5.4 smd: 1(-4.95,0) 2(4.95,0)
  silkscreen extent -6,-6 6,6, body extent -6,-6 6,6, height 10.01
WL-SMCW_GREEN [mm] "WURTH"
  rect 0.8x0.8 smd: 1(-0.8,0) 2(0.8,0)
  silkscreen extent -1.9,-0.8 1.2,0.8, body extent -0.85,-0.45 0.85,0.45, height 0.8

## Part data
C1: library part EKYB101ELL391MK35S, "CAP, AL, 220 µF, 100 V, +/- 20%, 0.039 ohm, TH"
C2 C5 C6 C7 C10 C11 C12 C21 C22 C23 C42 C45: "CAP, CERM, 3.3 µF, 100 V, +/- 20%, X7S, 1206_190"
C3 C8 C19: "CAP, CERM, 2.2 µF, 10 V, +/- 10%, X5R, 0402"
C4 C9 C20: "CAP, CERM, 0.1 µF, 100 V, +/- 5%, C0G/NP0, 1206_190"
C13 C14 C24 C47 C50 C54 C59: "CAP, CERM, 0.1 µF, 16 V, +/- 10%, X7R, 0402"
C15 C16 C17 C18 C25 C26: "CAP, CERM, 47 pF, 25 V, +/- 5%, C0G/NP0, 0402"
C27 C32: "CAP, CERM, 0.1 µF, 10 V, +/- 10%, X7R, 0402"
C28 C29 C30 C31 C33 C34 C35 C36: "CAP, CERM, 2200 pF, 16 V, +/- 10%, X7R, 0603"
C37: "CAP, CERM, 0.01 µF, 16 V, +/- 10%, X5R, 0402"
C38: "CAP, CERM, 3300 pF, 100 V, +/- 10%, X7R, 0603"
C39: "CAP, CERM, 0.01 µF, 50 V, +/- 10%, X7R, 0805"
C40: "CAP, CERM, 100 µF, 10 V, +/- 20%, X5R, 1206_190"
C41: "CAP, CERM, 0.1 µF, 25 V, +/- 20%, X7R, 0402"
C43 C44: "CAP, CERM, 0.1 µF, 100 V, +/- 10%, X7R, 0603"
C46: "CAP, CERM, 1 µF, 10 V, +/- 10%, X7R, 0603"
C48: "CAP, CERM, 1 µF, 10 V, +/- 10%, X7S, AEC-Q200 Grade 1, 0402"
C49: "CAP, CERM, 100 µF, 6.3 V, +/- 20%, X5R, 1206"
C51 C55 C57 C60: "CAP, CERM, 0.033 µF, 10 V, +/- 10%, X7R, 0402"
C52 C56 C63: "CAP, CERM, 1500 pF, 25 V, +/- 5%, C0G/NP0, 0402"
C53 C58 C61 C62 C64: "CAP, CERM, 0.1 µF, 16 V, +/- 10%, X7R, 0603"
D1 D2 D3 D4: "Diode, Schottky, 70 V, 0.07 A, SOD-523"
D5 D6: "LED, Green, SMD"
FID1 FID2 FID3: "Fiducial mark.  There is nothing to buy or mount."
J1 J2: "Connector, Receptacle, 100mil, 10x2, Gold plated, TH"
J3: "Terminal Block, 3x1, 5.08 mm, Tin, TH"
J4: "Terminal Block, 2-pole, 200mil, TH"
J5 J6: "Header, 100mil, 2x1, Tin, TH"
L1: "Inductor, Shielded Drum Core, Ferrite, 470 µH, 1.4 A, 0.56 ohm, SMD"
L2: "Inductor, Shielded, Ferrite, 33 µH, 0.085 A, 1.4 ohm, SMD"
L3: "Ferrite Bead, 300 ohm @ 100 MHz, 0.2 A, 0402"
LBL1: library part THT-14-423-10, "Thermal Transfer Printable Labels, 0.650\" W x 0.200\" H - 10,000 per roll"
LOGO1 LOGO5: library part IEC_HotSurface, "IEC 61010-1 Hot Surface Warning"
Logo3: library part Pb-Free
Logo4: library part FCC_disclaimer, "FCC_disclaimer"
NT1: "Single point connection between nets."
R1 R2 R53 R54: "RES, 0, 5%, 0.1 W, 0603"
R3 R4 R9 R22 R23 R46 R47 R49 R51 R52 R57 R58 R60 R63 R64 R68 R71 R72 R73 R75 R76: "RES, 0, 5%, 0.063 W, 0402"
R5 R6 R7 R8 R10 R11: "RES, 20.0, 1%, 0.063 W, 0402"
R12 R13 R14 R15 R16 R17 R18 R19 R20: "RES, 20, 5%, 0.063 W, 0402"
R21 R24 R25 R26 R27 R28 R29 R30 R31 R32 R33 R34 R35 R36 R37 R38: "RES, 10 k, 5%, 0.063 W, 0402"
R39: "RES, 1.2 k, 5%, 0.063 W, 0402"
R40: "RES, 470 k, 5%, 0.063 W, 0402"
R41 R48: "RES, 10.0 k, 1%, 0.063 W, 0402"
R42: "RES, 510 k, 1%, 0.1 W, 0603"
R43: "RES, 100 k, 5%, 0.1 W, 0603"
R44: "RES, 3.24 k, 1%, 0.063 W, 0402"
R45: "RES, 20 k, 5%, 0.063 W, 0402"
R50: "RES, 820, 5%, 0.063 W, 0402"
R55 R61 R69: "RES, 0.005, 1%, 3 W, AEC-Q200 Grade 0, 2512"
R56 R62 R66 R70: "RES, 100 k, 1%, 0.063 W, 0402"
R59 R65 R67 R74: "RES, 4.22 k, 1%, 0.063 W, 0402"
TP1 TP2: "Test Point, Miniature, Black, TH"
U1 U2 U3: library part PLMG5200MOFT, "100V GaN Half Bridge Power Module, MOF0009A"
U4: "8-BIT DUAL-SUPPLY BUS TRANSCEIVER WITH CONFIGURABLE VOLTAGE TRANSLATION AND 3-STATE OUTPUTS, RHL0024A"
U5: "100V, 300mA Constant On-Time Synchronous Buck Regulator, DDA0008B"
U6: "Automotive Grade, Low-Power, Easy-to-Use, Temperature Switch in MicroPackage, DRL0006A"
U7: "500mA Low Dropout CMOS Linear Regulators Stable with Ceramic Output Capacitors, 6-pin LLP, Pb-Free"
U8 U9 U11: "Wide Common-Mode Range, Voltage Output, High or Low-Side Bi-Directional Zero-Drift Current Shunt Monitor, PW0008A"
U10: "30 ppm / degC Drift, 3.9 uA Voltage Reference, -40 to 125 degC, 3-pin SOT-23 (DBZ), Green (RoHS & no Sb/Br)"
ZZ1: library part AssemblyNoteLabel
ZZ2 ZZ3 ZZ4: library part AssemblyNote

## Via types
v1: diameter 19.68, hole 7.87, Top Layer to Bottom Layer, 168 vias
v2: diameter 25.98, hole 12.99, Top Layer to Bottom Layer, tented top, 22 vias
v3: diameter 34, hole 16, Top Layer to Bottom Layer, 1 vias

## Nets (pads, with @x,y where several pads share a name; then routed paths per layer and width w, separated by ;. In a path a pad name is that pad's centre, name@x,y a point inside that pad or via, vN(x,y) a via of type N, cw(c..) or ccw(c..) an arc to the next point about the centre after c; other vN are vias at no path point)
3V3: C27.1 C47.1 C50.2 C54.2 C59.2 D1.1 D2.1 D3.1 D4.1 J6.1 R22.2 R28.1 R30.2 R46.2 R47.2 R48.2 R49.2 R50.2 R73.2 U4.1 U6.5 U8.5 U9.5 U11.5 | length 1146.5
  Top Layer w10: U11.5@1889.24,1986.06 U11.5@1888.61,1985.43 1946.19,1985.43 C59.2@1948.43,1987.67 ; 1915.55,1988 1915.93,1988.38 v1@1915.93,2009.98 ; U9.5@2755.18,1988.19 2755.82,1988.82 2778.95,1988.82 v1(2778.95,2013.82) ; 2780.33,1987.44 C54.2@2818.95,1987.44 ; R50.2@2879.71,2734.12 R50.2@2880,2734.41 ; v1(3239.27,2007.3) R73.2@3239.27,2026.42 ; U8.5@3625.96,1986.11 3626.59,1986.74 3649.73,1986.74 v1(3649.73,2011.74) ; 3651.1,1985.36 C50.2@3689.73,1985.36 ; v1(4044.64,2569.21) 4068.84,2545.01 D3.1@4068.84,2532.36 ; D1.1@4352.33,2505.73 4352.68,2505.38 v1(4352.68,2461.42)
  Top Layer w25: v1(2845.03,2733.06) R50.2@2877.93,2733.06
  Bottom Layer w10: U6.5@3743.35,1231.73 U6.5@3742.45,1232.64 3769.62,1232.64 R47.2@3789.35,1212.91 ; R46.2@3787.27,843.67 3799.72,856.12 v2(3799.72,878.08) ; R47.2@3788.75,1212.32 3801.43,1212.32 ; R46.2@3790.93,846.6 3793.13,844.4 R48.2@3844.2,844.4 ; v1(3800.63,1106.22) 3832.92,1138.51 C47.1@3832.92,1193.54 ; 3801.37,1212.09 3811.15,1212.09 3813.42,1209.82 3813.42,1200.34 3819.61,1194.15 C47.1@3835.34,1194.15 ; D4.1@4017.65,2537.17 4024.13,2543.65 4024.13,2546.92 4044.64,2567.43 v1(4044.64,2569.21) ; D2.1@4202.25,2533.68 D2.1@4205.45,2533.68 ; D2.1@4207.57,2531.79 4209.45,2533.67 v1(4237.56,2533.67) ; U4.1@4424.17,1405.75 4426.02,1403.9 4426.02,1381.5 C27.1@4471.04,1336.48 ; R30.2@4458.75,1600.77 4458.75,1633.92 v1@4469.97,1645.14 ; R28.1@4473.77,1298.69 4473.77,1312.76 ; C27.1@4473.77,1337.71 4473.77,1312.76 ; v1@4501.44,1315.5 4498.7,1312.76 4473.77,1312.76 ; v1@4502.88,1315.5 4521.36,1333.97 R22.2@4521.36,1458.35
  other v1: 4503.24,1316.22 4470.12,1645.95 1915.02,2009.32 3088.56,2507.33 3097.79,2531.13 3074.71,2532.56
3V3_LAUNCHPAD_IN: J1.1 J6.2 | length 1180.5
  Internal Layer 2 w40: J6.2@3328.63,2768.2 3394.97,2834.54 4366.26,2834.54 J1.1@4447.83,2752.97
5V: C48.1 J5.1 L3.2 R3.2 R4.2 R9.2 R23.2 R39.2 U7.1 U7.6 | length 3319
  Top Layer w10: R9.2@1963.05,1775.16 v1@1989.42,1775.16 ; C48.1@2760,2600.78 C48.1@2760,2603.07 ; 2780.53,2497.95 2783.43,2497.95 ; 2783.43,2498.63 2783.43,2497.95 ; 2784.06,2500.43 2784.06,2497.95 2783.43,2497.95 ; R4.2@2829.62,1777.91 v1@2856,1777.91 ; R3.2@3700.39,1775.83 v1@3726.77,1775.83
  Top Layer w20: C48.1@2756.46,2604.31 2730.13,2577.97 2730.13,2548.17 2740.6,2537.7 2740.78,2537.7 2780.53,2497.95 ; v1@2758.69,2322 2815.5,2265.18 v1(2959.29,2265.18) ; C48.1@2760,2603.07 2794.8,2603.07 2799.92,2608.19 U7.6@2832.6,2608.19 ; C48.1@2762.01,2605.08 v1(2762.01,2635.35) 2762.01,2738.04 2824.23,2800.26 R39.2@2824.23,2818.56 ; 2784.06,2497.95 U7.1@2832.6,2497.95 ; v1@2966.14,2114.18 L3.2@3080.41,2114.18
  Internal Layer 2 w20: v1(2961.46,2118.26) v1@2961.46,2261.77
  Internal Layer 2 w50: 1993.05,1722.2 v1(1993.05,1771.54) ; 2859.62,1727.92 v1(2859.62,1774.29) ; 3730.39,1736.76 v1(3730.39,1772.21)
  Internal Layer 2 w100: 1683.53,1730.64 1637.04,1777.13 J5.1@1637.04,2189.01 1637.04,2101.61 1908.66,2101.61 2020.59,2213.53 2618.53,2213.53 2764.2,2359.2 v1@2764.2,2639.63
  Bottom Layer w10: v1(1993.05,1771.54) v1@1993.69,1770.9
  Bottom Layer w20: R23.2@4104.45,1696.3 4106.04,1697.89 v1(4106.04,1732.47)
  other v1: 2759.62,2320.65 2761.76,2658.09 2762.75,2677.86
GND: C3.2 C8.2 C15.2 C16.2 C17.2 C18.2 C19.2 C25.2 C26.2 C27.2 C28.2 C29.2 C30.2 C31.2 C32.2 C33.2 C34.2 C35.2 C36.2 C40.2 C41.2 C42.2 C43.2 C44.2 C45.2 C46.2 C48.2 C49.2 C50.1 C51.2 C53.1 C54.1 C55.2 C57.2 C58.1 C59.1 C60.2 C61.1 C62.1 C64.1 D5.1 D6.1 J1.4 J2.2 NT1.2 R1.2 R2.2 R21.1 R24.1 R25.1 R26.1 R27.1 R29.1 R31.1 R32.1 R33.1 R34.1 R35.1 R36.1 R37.1 R38.1 R44.1 R45.1 R54.1 R59.1 R65.1 R67.1 R74.1 TP1.1 U1.7 U2.7 U3.7 U4.11 U4.12 U4.13 U5.1 U5.9 U7.2 U7.3 U7.7 U8.1 U8.4 U8.6 U9.1 U9.4 U9.6 U10.3 U11.1 U11.4 U11.6 | length 4514.2
  Top Layer w10: C60.2@1751.73,1796.04 1751.73,1757.3 1750.08,1755.65 1752.58,1753.15 U11.1@1811.84,1753.15 1811.84,1792.4 1821.88,1802.44 1881.64,1802.44 1888.61,1795.47 U11.4@1888.61,1753.15 ; U11.6@1863.02,1985.43 1863.02,1955.91 1877.86,1941.06 1955.57,1941.06 C59.1@1956.1,1940.54 ; v1(1935.24,1656.9) 1960.16,1631.97 C19.2@1963.32,1631.97 ; C64.1@1957.2,2055.62 1957.58,2056.01 v2(1999.23,2056.01) ; C19.2@1964.37,1634.6 1964.47,1634.61 C19.2@1974.8,1635.2 ; 1980,1630 U3.7@2038.41,1630 2041.51,1630 2067.03,1655.52 2067.03,1692.1 2039.92,1719.21 C26.2@2039.92,1750 2039.92,1768.41 v1(2053.05,1781.54) ; v1(2233.05,1781.54) 2237.17,1777.42 C25.2@2237.17,1750 ; R65.1@2614.86,1801.27 2614.86,1761.23 2620.18,1755.91 U9.1@2678.41,1755.91 2678.41,1795.16 2688.45,1805.2 2748.22,1805.2 2755.18,1798.23 U9.4@2755.18,1755.91 ; C57.2@2661.32,2428.21 v2(2682.97,2406.56) R67.1@2664.63,2388.21 ; U9.6@2732.07,1985.71 U9.6@2729.59,1988.19 2729.59,1958.66 2744.44,1943.82 v1(2787.67,1943.82) 2815.33,1943.82 C54.1@2818.95,1940.2 ; C58.1@2790.45,2053.82 v2(2828.95,2053.82) ; v1@2801.45,1658.1 2801.45,1641.02 2810.9,1631.57 C8.2@2831.38,1631.57 ; C8.2@2825.29,1633.29 C8.2@2827.02,1633.29 ; C8.2@2830.83,1632.98 2831.06,1632.76 U2.7@2904.99,1632.76 2908.09,1632.76 2933.61,1658.28 2933.61,1694.86 2906.5,1721.97 2906.5,1771.17 v1(2919.62,1784.29) ; C8.2@2832.8,1639.65 C8.2@2835.15,1637.3 ; U7.7@2870,2551.4 v1(2870,2533.39) U7.2@2870,2497.95 U7.3@2907.4,2497.95 ; D5.1@2997.67,2804.99 2997.67,2694.62 D6.1@3001.5,2690.79 D6.1@3010.57,2690.79 ; C17.2@3099.62,1759.91 v1(3099.62,1784.29) ; v1@3179.35,2017.88 C61.1@3179.35,2053.9 ; U10.3@3212.6,2264.49 3214.53,2266.42 3287.89,2266.42 3307.89,2246.42 3307.89,2118 C62.1@3305.29,2115.4 ; R59.1@3488.49,1798.37 3488.49,1759.06 3492.78,1754.77 U8.1@3548.78,1754.77 ; v1(3524.3,2400.65) 3524.3,2436.12 C28.2@3527.11,2438.92 ; U8.1@3549.19,1753.82 3549.19,1793.07 3559.23,1803.11 3618.99,1803.11 3625.96,1796.14 U8.4@3625.96,1753.82 ; U8.6@3602.85,1983.62 U8.6@3600.37,1986.11 3600.37,1956.58 3615.21,1941.74 v1(3658.44,1941.74) 3686.1,1941.74 C50.1@3689.73,1938.11 ; v1@3641.88,2414.57 3642.25,2414.95 C29.2@3642.25,2452.79 ; C53.1@3661.22,2051.74 v2(3699.73,2051.74) ; v1@3672.21,1656.43 C3.2@3702.29,1631.55 ; C3.2@3704.02,1629.82 U1.7@3775.76,1630.67 3778.86,1630.67 3804.38,1656.19 3804.38,1692.78 3777.27,1719.89 C16.2@3777.27,1750.67 3777.27,1769.08 v1(3790.39,1782.21) ; v1@3749.59,2412.65 3752.99,2416.05 C30.2@3752.99,2451.28 ; v1(3838.46,2412.88) 3854.62,2429.04 C31.2@3854.62,2451.85 ; v1(3970.39,1782.21) 3974.51,1778.09 C15.2@3974.51,1750.67 ; v1@4135.56,2380.17 C35.2@4135.56,2428.04 ; v1@4288.57,2387.74 C36.2@4288.57,2432.99
  Top Layer w20: C40.2@1916.93,2320 C45.2@1993.07,2320 1993.07,2360.79 U5.1@2075,2442.72 2075,2535 U5.9@2090,2550 ; C48.2@2760,2563.07 2849.99,2563.07 U7.7@2861.66,2551.4
  Top Layer w30: C41.2@1873.62,2240 1916.93,2283.31 ; U7.7@2906.42,2545.32 2965.59,2486.14 C49.2@3010,2486.14
  Internal Layer 1 w10: 4021.58,1131.65 v1@4028.4,1138.48
  Bottom Layer w10: v1(3838.46,2412.88) 3852.55,2426.97 3852.55,2450.45 ; R29.1@4003.62,1160 4007.56,1160 v1(4029.21,1138.35) 4034.72,1138.35 R27.1@4056.38,1160 ; R26.1@4203.62,1160 4225.28,1138.35 v1(4229.21,1138.35) 4234.72,1138.35 R25.1@4256.38,1160 ; U4.13@4215.51,1464.8 4207.31,1464.8 4198.7,1456.2 4198.7,1414.43 4207.38,1405.75 U4.12@4215.51,1405.75 4208.62,1398.86 v1(4208.62,1380) 4218.62,1370 U4.11@4230.94,1370 ; R38.1@4220.59,1270.98 4220.59,1266.1 v1(4240.09,1246.6) 4240.09,1250.48 R37.1@4260.59,1270.98 ; R36.1@4240,1633.62 R35.1@4240,1686.38 ; R34.1@4320,1633.62 v1@4320,1657.56 ; R33.1@4320,1686.38 4321.65,1684.72 v1@4321.65,1659.21 ; R32.1@4400,1630.23 R31.1@4400,1682.62 ; R24.1@4408.76,1154.86 R24.1@4403.62,1160 4407.56,1160 v1(4429.21,1138.35) ; v1@4434.72,1138.35 R21.1@4456.38,1160 ; C27.2@4474.24,1387.23 C32.2@4474.24,1457.41
  Bottom Layer w60: NT1.2@1676.73,1615.86 1676.73,1689.4
  other v1: 3899.49,1096.11 4464.83,1421.09 4486.21,1420.76 2801.42,1657.16 3672.06,1657.16 4399.49,1662.14 4320.87,1663.1 4239.78,1664.24 1851.76,1802.44 3589.11,1803.11 2718.33,1805.2 3177.89,2016.42 3307.89,2186.42 4135.44,2383.87 4288.9,2388.18 3947.02,2398.52 3640.98,2408.34 3752.3,2410.09 2838.5,2553.07 2901.5,2553.07 2870,2572.76 2996.61,2745.19
  other v2: 1911.43,1940.31 2126.38,2526.38 2173.62,2526.38 2126.38,2573.62 2173.62,2573.62 2538.83,2575.51 2538.83,2616.47 2538.83,2654.87 2538.83,2689.85
IA: R16.1 U8.8 | length 687.4
  Top Layer w10: U8.8@3549.19,1986.11 3549.19,2087.94 3715.69,2254.45 3715.69,2324.93 3803.44,2412.68 ; 3803.79,2413.03 3803.44,2412.68 ; R16.1@3804.72,2567.16 3803.44,2565.88 3803.44,2412.68
IB: R18.1 U9.8 | length 1418.8
  Top Layer w10: U9.8@2678.41,1988.19 2678.41,2109.71 2728.45,2159.75 3016.26,2159.75 3166.51,2310 3549.45,2310 3551.52,2307.93 3563.16,2307.93 3565.23,2310 3593.2,2310 3703.66,2420.46 R18.1@3703.66,2562.09
IC: R19.1 U11.8 | length 2161.8
  Top Layer w10: U11.8@1806.21,1991.06 U11.8@1811.84,1985.43 1811.84,2068.28 1839.73,2096.18 1903.42,2096.18 1914.72,2107.48 2018.31,2107.48 2025.27,2100.51 2540.25,2100.51 2549.07,2109.33 ; 2549.98,2108.34 2650,2200 2978,2200 3123.75,2345.75 3509.58,2345.75 3591.76,2427.92 3591.76,2562.09 R19.1@3595.26,2565.59
"NC (5V_LAUNCHPAD)": J1.2
NetC3_1: C3.1 R3.1 U1.6 | length 108.5
  Top Layer w10: C3.1@3700.39,1678.49 R3.1@3700.39,1728.59 ; C3.1@3712.15,1683.11 U1.6@3770.56,1683.11
NetC8_1: C8.1 R4.1 U2.6 | length 108.5
  Top Layer w10: C8.1@2829.62,1680.58 R4.1@2829.62,1730.67 ; C8.1@2841.38,1685.2 U2.6@2899.79,1685.2
NetC13_1: C13.1 U1.2 | length 64.9
  Top Layer w10: U1.2@3976.55,1630.67 4009.86,1630.67 4018.68,1639.49 C13.1@4037.8,1639.49
NetC13_2: C13.2 U1.3 | length 64.9
  Top Layer w10: U1.3@3976.55,1677.92 4002.61,1677.92 4011.43,1686.74 C13.2@4037.8,1686.74
NetC14_1: C14.1 U2.2 | length 64.9
  Top Layer w10: U2.2@3105.77,1632.76 3139.09,1632.76 3147.91,1641.57 C14.1@3167.03,1641.57
NetC14_2: C14.2 U2.3 | length 64.9
  Top Layer w10: U2.3@3105.77,1680 3131.84,1680 3140.65,1688.82 C14.2@3167.03,1688.82
NetC15_1: C15.1 R5.1 U1.4 | length 152.8
  Top Layer w10: 3900.39,1744.87 R5.1@3900.39,1800.4 ; U1.4@3911.58,1689.73 3911.58,1693.68 3902.15,1703.11 3902.15,1743.11 C15.1@3942.15,1743.11
NetC16_1: C16.1 R6.1 U1.5 | length 153.6
  Top Layer w10: C16.1@3812.15,1739.92 3852.15,1739.92 3852.15,1701.16 U1.5@3840.72,1689.73 ; 3850.39,1741.68 R6.1@3850.39,1800.4
NetC17_1: C17.1 R7.1 U2.4 | length 152.8
  Top Layer w10: 3029.62,1746.95 R7.1@3029.62,1802.48 ; U2.4@3040.81,1691.81 3040.81,1695.76 3031.38,1705.2 3031.38,1745.2 C17.1@3071.38,1745.2
NetC18_1: C18.1 R8.1 U2.5 | length 113.6
  Top Layer w10: U2.5@2969.95,1691.81 2981.38,1703.24 2981.38,1742.01 ; 2979.62,1743.76 R8.1@2979.62,1802.48
NetC19_1: C19.1 R9.1 U3.6 | length 108.5
  Top Layer w10: C19.1@1963.05,1677.82 R9.1@1963.05,1727.91 ; C19.1@1974.8,1682.44 U3.6@2033.21,1682.44
NetC24_1: C24.1 U3.2 | length 64.9
  Top Layer w10: U3.2@2239.2,1630 2272.52,1630 2281.33,1638.82 C24.1@2300.46,1638.82
NetC24_2: C24.2 U3.3 | length 64.9
  Top Layer w10: U3.3@2239.2,1677.24 2265.26,1677.24 2274.08,1686.06 C24.2@2300.46,1686.06
NetC25_1: C25.1 R10.1 U3.4 | length 152.8
  Top Layer w10: 2163.05,1744.2 R10.1@2163.05,1799.73 ; U3.4@2174.24,1689.06 2174.24,1693.01 2164.8,1702.44 2164.8,1742.44 C25.1@2204.8,1742.44
NetC26_1: C26.1 R11.1 U3.5 | length 153.6
  Top Layer w10: C26.1@2074.8,1739.25 2114.8,1739.25 2114.8,1700.49 U3.5@2103.37,1689.06 ; 2113.05,1741.01 R11.1@2113.05,1799.73
NetC28_1: C28.1 J1.20 R17.2 R20.2 | length 280.1
  Top Layer w10: R17.2@3434.9,2676.61 3464.19,2647.32 J1.20@3548.28,2647.32 ; C28.1@3523.9,2506.32 3523.9,2554.96 3548.45,2579.51 J1.20@3548.45,2650.74
NetC29_1: C29.1 J1.18 R19.2 | length 136.1
  Top Layer w10: C29.1@3644.8,2516.05 3650,2521.25 J1.18@3650,2650
NetC30_1: C30.1 J1.16 R18.2 | length 133.7
  Top Layer w10: J1.16@3750,2650 3750,2523.33 C30.1@3754.95,2518.38
NetC31_1: C31.1 J1.14 R16.2 | length 135.2
  Top Layer w10: J1.14@3850,2650 3850,2517.16 C31.1@3851.7,2515.46
NetC32_1: C32.1 R22.1 R23.1 U4.23 U4.24 | length 646.2
  Top Layer w10: v1(4156.38,1662.98) 4188.66,1630.7 4447.51,1630.7 v1@4524.96,1553.26
  Bottom Layer w10: R23.1@4153.31,1693.67 4153.31,1667.6 v1@4156.56,1664.35 ; U4.23@4409.41,1500.24 4419.76,1500.24 4424.17,1495.83 U4.24@4424.17,1464.8 ; 4425.08,1484.5 4444.26,1503.68 4519.89,1503.68 4524.72,1508.51 v1(4524.72,1552.83)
